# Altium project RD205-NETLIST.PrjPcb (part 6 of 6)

## Sheet 13.SchDoc
size 398 x 287 mm
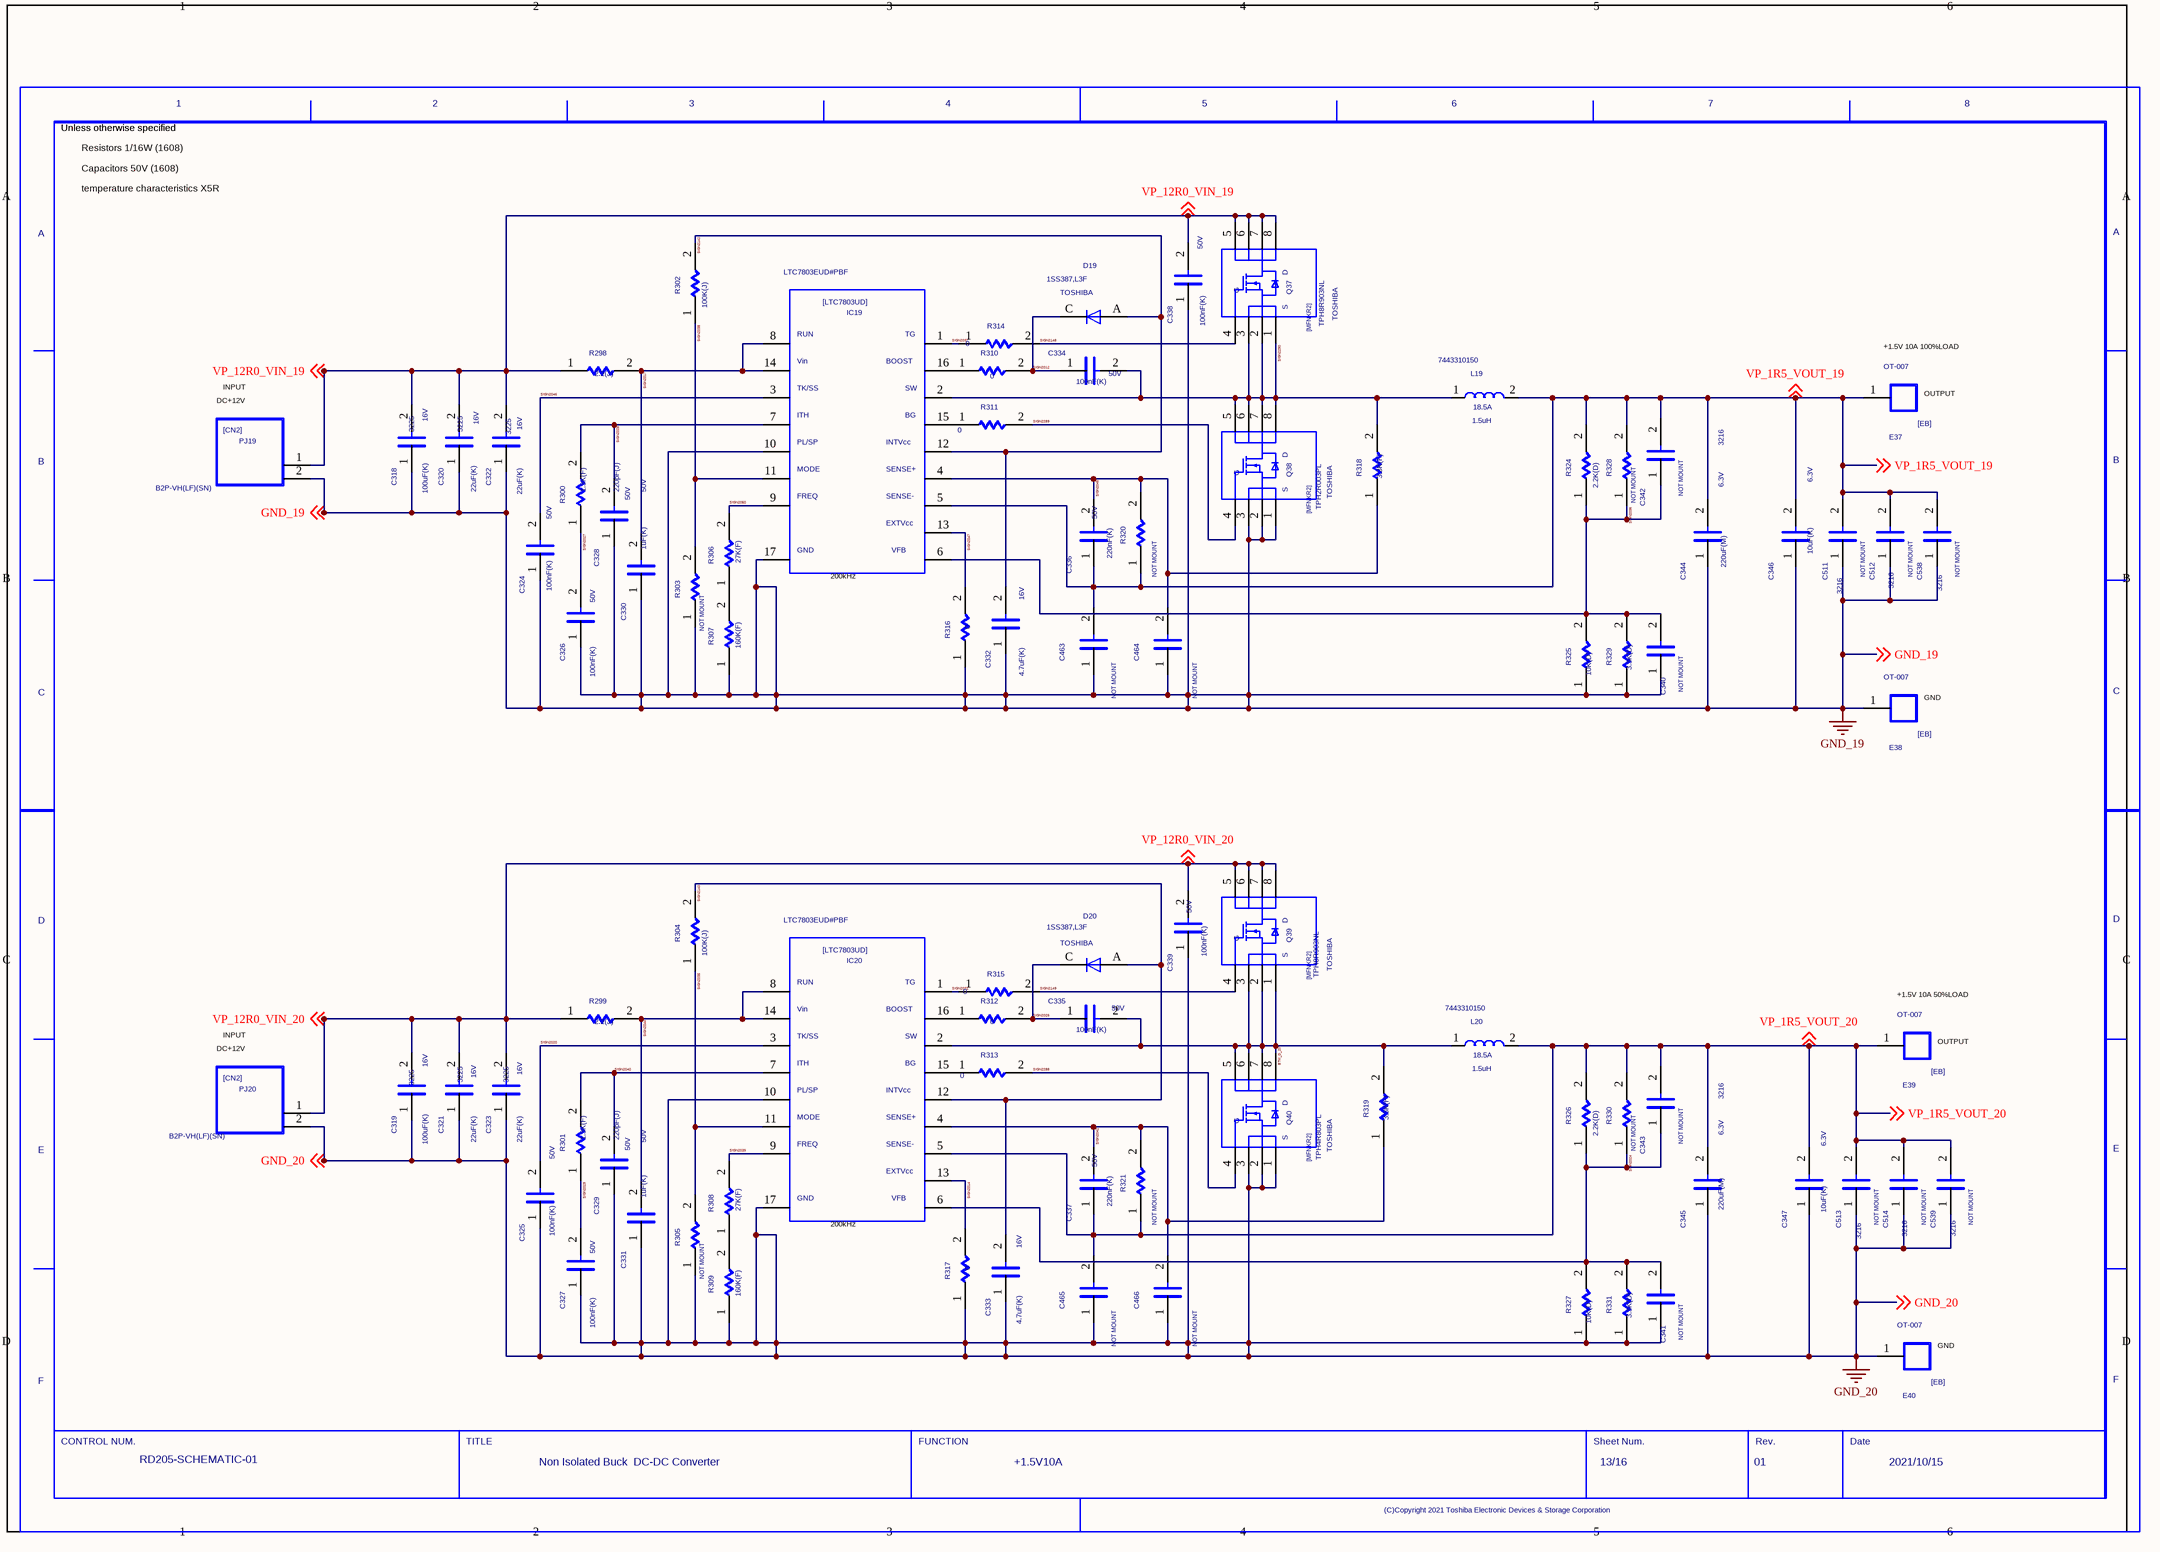
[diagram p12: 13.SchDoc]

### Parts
(Parts that share a designator on the sheet are numbered #1, #2 ... from top to bottom, then left to right.)
C318  SIZECODESMD: 3225  VAL2: 16V  VAL1: 100uF(K)  (hidden comment: C)
C319  SIZECODESMD: 3225  VAL2: 16V  VAL1: 100uF(K)  (hidden comment: C)
C320  SIZECODESMD: 3225  VAL2: 16V  VAL1: 22uF(K)  (hidden comment: C)
C321  SIZECODESMD: 3225  VAL2: 16V  VAL1: 22uF(K)  (hidden comment: C)
C322  SIZECODESMD: 3225  VAL2: 16V  VAL1: 22uF(K)  (hidden comment: C)
C323  SIZECODESMD: 3225  VAL2: 16V  VAL1: 22uF(K)  (hidden comment: C)
C324  VAL2: 50V  VAL1: 100nF(K)  (hidden comment: C)
C325  VAL2: 50V  VAL1: 100nF(K)  (hidden comment: C)
C326  VAL2: 50V  VAL1: 100nF(K)  (hidden comment: C)
C327  VAL2: 50V  VAL1: 100nF(K)  (hidden comment: C)
C328  VAL2: 50V  VAL1: 220pF(J)  (hidden comment: C)
C329  VAL2: 50V  VAL1: 220pF(J)  (hidden comment: C)
C330  VAL2: 50V  VAL1: 1uF(K)  (hidden comment: C)
C331  VAL2: 50V  VAL1: 1uF(K)  (hidden comment: C)
C332  VAL2: 16V  VAL1: 4.7uF(K)  (hidden comment: C)
C333  VAL2: 16V  VAL1: 4.7uF(K)  (hidden comment: C)
C334  VAL2: 50V  VAL1: 100nF(K)  (hidden comment: C)
C335  VAL2: 50V  VAL1: 100nF(K)  (hidden comment: C)
C336  VAL2: 50V  VAL1: 220nF(K)  (hidden comment: C)
C337  VAL2: 50V  VAL1: 220nF(K)  (hidden comment: C)
C338  VAL2: 50V  VAL1: 100nF(K)  (hidden comment: C)
C339  VAL2: 50V  VAL1: 100nF(K)  (hidden comment: C)
C340  NOTMOUNT: NOT MOUNT  (hidden comment: C)
C341  NOTMOUNT: NOT MOUNT  (hidden comment: C)
C342  NOTMOUNT: NOT MOUNT  (hidden comment: C)
C343  NOTMOUNT: NOT MOUNT  (hidden comment: C)
C344  SIZECODESMD: 3216  VAL2: 6.3V  VAL1: 220uF(M)  (hidden comment: C)
C345  SIZECODESMD: 3216  VAL2: 6.3V  VAL1: 220uF(M)  (hidden comment: C)
C346  VAL2: 6.3V  VAL1: 10uF(K)  (hidden comment: C)
C347  VAL2: 6.3V  VAL1: 10uF(K)  (hidden comment: C)
C463  NOTMOUNT: NOT MOUNT  (hidden comment: C)
C464  NOTMOUNT: NOT MOUNT  (hidden comment: C)
C465  NOTMOUNT: NOT MOUNT  (hidden comment: C)
C466  NOTMOUNT: NOT MOUNT  (hidden comment: C)
C511  NOTMOUNT: NOT MOUNT  SIZECODESMD: 3216  (hidden comment: C)
C512  NOTMOUNT: NOT MOUNT  SIZECODESMD: 3216  (hidden comment: C)
C513  NOTMOUNT: NOT MOUNT  SIZECODESMD: 3216  (hidden comment: C)
C514  NOTMOUNT: NOT MOUNT  SIZECODESMD: 3216  (hidden comment: C)
C538  NOTMOUNT: NOT MOUNT  SIZECODESMD: 3216  (hidden comment: C)
C539  NOTMOUNT: NOT MOUNT  SIZECODESMD: 3216  (hidden comment: C)
D19  USERCOMPTEXT3: TOSHIBA  VAL3: 1SS387,L3F  (hidden comment: D)
D20  USERCOMPTEXT3: TOSHIBA  VAL3: 1SS387,L3F  (hidden comment: D)
E37  VAL3: OT-007  (hidden comment: EB)
E38  VAL3: OT-007  (hidden comment: EB)
E39  VAL3: OT-007  (hidden comment: EB)
E40  VAL3: OT-007  (hidden comment: EB)
IC19  VAL3: LTC7803EUD#PBF  (hidden comment: LTC7803UD)
IC20  VAL3: LTC7803EUD#PBF  (hidden comment: LTC7803UD)
L19  VAL3: 7443310150  VAL2: 18.5A  VAL1: 1.5uH  (hidden comment: L)
L20  VAL3: 7443310150  VAL2: 18.5A  VAL1: 1.5uH  (hidden comment: L)
PJ19  VAL3: B2P-VH(LF)(SN)  (hidden comment: CN2)
PJ20  VAL3: B2P-VH(LF)(SN)  (hidden comment: CN2)
Q37  USERCOMPTEXT3: TOSHIBA  VAL3: TPH8R903NL  (hidden comment: MFNKR2)
Q38  USERCOMPTEXT3: TOSHIBA  VAL3: TPH2R003PL  (hidden comment: MFNKR2)
Q39  USERCOMPTEXT3: TOSHIBA  VAL3: TPH8R903NL  (hidden comment: MFNKR2)
Q40  USERCOMPTEXT3: TOSHIBA  VAL3: TPH4R803PL  (hidden comment: MFNKR2)
R298  VAL1: 2.2(J)  (hidden comment: R)
R299  VAL1: 2.2(J)  (hidden comment: R)
R300  VAL1: 1.3K(F)  (hidden comment: R)
R301  VAL1: 1.3K(F)  (hidden comment: R)
R302  VAL1: 100K(J)  (hidden comment: R)
R303  NOTMOUNT: NOT MOUNT  (hidden comment: R)
R304  VAL1: 100K(J)  (hidden comment: R)
R305  NOTMOUNT: NOT MOUNT  (hidden comment: R)
R306  VAL1: 27K(F)  (hidden comment: R)
R307  VAL1: 160K(F)  (hidden comment: R)
R308  VAL1: 27K(F)  (hidden comment: R)
R309  VAL1: 160K(F)  (hidden comment: R)
R310  VAL1: 0  (hidden comment: R)
R311  VAL1: 0  (hidden comment: R)
R312  VAL1: 0  (hidden comment: R)
R313  VAL1: 0  (hidden comment: R)
R314  VAL1: 0  (hidden comment: R)
R315  VAL1: 0  (hidden comment: R)
R316  VAL1: 0  (hidden comment: R)
R317  VAL1: 0  (hidden comment: R)
R318  VAL1: 3.3K(F)  (hidden comment: R)
R319  VAL1: 3.3K(F)  (hidden comment: R)
R320  NOTMOUNT: NOT MOUNT  (hidden comment: R)
R321  NOTMOUNT: NOT MOUNT  (hidden comment: R)
R324  VAL1: 2.2K(D)  (hidden comment: R)
R325  VAL1: 10K(D)  (hidden comment: R)
R326  VAL1: 2.2K(D)  (hidden comment: R)
R327  VAL1: 10K(D)  (hidden comment: R)
R328  NOTMOUNT: NOT MOUNT  (hidden comment: R)
R329  VAL1: 3.3K(D)  (hidden comment: R)
R330  NOTMOUNT: NOT MOUNT  (hidden comment: R)
R331  VAL1: 3.3K(D)  (hidden comment: R)
U?#13  DATE: 2021/10/15  SHEETNUMBER: 13/16  TITLE: Non Isolated Buck / DC-DC Converter  REVISION: 01  DRAWINGNUMBER: RD205-SCHEMATIC-01  FUNCTION: +1.5V10A  (hidden comment: WAKU_DEF100)

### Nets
GND_19: C318.1 C320.1 C322.1 C324.1 C326.1 C328.1 C330.1 C332.1 C338.1 C340.1 C344.1 C346.1 C463.1 C464.1 C511.1 C512.1 C538.1 E38.1 IC19.10 IC19.17 PJ19.2 Q38.1 Q38.2 Q38.3 R303.1 R307.1 R316.1 R325.1 R329.1 ; off-sheet GND_19
GND_20: C319.1 C321.1 C323.1 C325.1 C327.1 C329.1 C331.1 C333.1 C339.1 C341.1 C345.1 C347.1 C465.1 C466.1 C513.1 C514.1 C539.1 E40.1 IC20.10 IC20.17 PJ20.2 Q40.1 Q40.2 Q40.3 R305.1 R309.1 R317.1 R327.1 R331.1 ; off-sheet GND_20
BTM_D_20: C335.2 IC20.2 L20.1 Q39.1 Q39.2 Q39.3 Q40.5 Q40.6 Q40.7 Q40.8 R319.2
SIGN2012: C334.1 D19.C R310.2
SIGN2014: IC20.13 R317.2
SIGN2017: C330.2 IC19.8 IC19.14 R298.2
SIGN2020: C325.2 IC20.3
SIGN2024: C341.2 C343.1 IC20.6 R326.1 R327.2 R330.1 R331.2
SIGN2026: C335.1 D20.C R312.2
SIGN2027: C326.2 R300.1
SIGN2028: C328.2 IC19.7 R300.2
SIGN2029: C327.2 R301.1
SIGN2031: IC20.1 R315.1
SIGN2035: IC20.11 R304.1 R305.2
SIGN2036: C340.2 C342.1 IC19.6 R324.1 R325.2 R328.1 R329.2
SIGN2037: IC19.1 R314.1
SIGN2038: IC19.11 R302.1 R303.2
SIGN2039: IC20.9 R308.2
SIGN2040: C329.2 IC20.7 R301.2
SIGN2042: C337.2 C466.2 IC20.4 R319.1 R321.2
SIGN2044: C331.2 IC20.8 IC20.14 R299.2
SIGN2045: C336.2 C464.2 IC19.4 R318.1 R320.2
SIGN2046: C324.2 IC19.3
SIGN2047: IC19.13 R316.2
SIGN2050: IC19.9 R306.2
SIGN2142: C332.2 D19.A IC19.12 R302.2
SIGN2143: C333.2 D20.A IC20.12 R304.2
SIGN2148: Q37.4 R314.2
SIGN2149: Q39.4 R315.2
SIGN2288: Q40.4 R313.2
SIGN2289: Q38.4 R311.2
SIGN2290: C334.2 IC19.2 L19.1 Q37.1 Q37.2 Q37.3 Q38.5 Q38.6 Q38.7 Q38.8 R318.2
VP_1R5_VOUT_19: C336.1 C342.2 C344.2 C346.2 C463.2 C511.2 C512.2 C538.2 E37.1 IC19.5 L19.2 R320.1 R324.2 R328.2 ; off-sheet VP_1R5_VOUT_19
VP_1R5_VOUT_20: C337.1 C343.2 C345.2 C347.2 C465.2 C513.2 C514.2 C539.2 E39.1 IC20.5 L20.2 R321.1 R326.2 R330.2 ; off-sheet VP_1R5_VOUT_20
VP_12R0_VIN_19: C318.2 C320.2 C322.2 C338.2 PJ19.1 Q37.5 Q37.6 Q37.7 Q37.8 R298.1 ; off-sheet VP_12R0_VIN_19
VP_12R0_VIN_20: C319.2 C321.2 C323.2 C339.2 PJ20.1 Q39.5 Q39.6 Q39.7 Q39.8 R299.1 ; off-sheet VP_12R0_VIN_20
NetIC19_15: IC19.15 R311.1
NetIC19_16: IC19.16 R310.1
NetIC20_15: IC20.15 R313.1
NetIC20_16: IC20.16 R312.1
NetR306_1: R306.1 R307.2
NetR308_1: R308.1 R309.2

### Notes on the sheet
- Unless otherwise specified
- Resistors 1/16W (1608)
- Capacitors 50V (1608)
- temperature characteristics X5R
- DC+12V
- INPUT
- (near E37) +1.5V 10A 100%LOAD
- (near E37) OUTPUT
- (near IC19) 200kHz
- (near E38) GND
- (near E39) +1.5V 10A 50%LOAD
- (near E39) OUTPUT
- (near IC20) 200kHz
- (near E40) GND

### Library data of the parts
C318 C319 = C: SQ_PART_MODEL: CON_100n; FNPARTSNAMEG: CHIP CERAMIC CAPACITOR (3225); USEINPARTSLIST: YES; OriginalSymbolOrigin: (2540,7620); MFSOLDERINGPROP: .; TEMPCHARACTERI2: B; MFFORMINGDIVP: KC; OUMECLASSIFICATION: セラミックコンデンサ; MFMOUNTSYMBOLP: 90; CDMASTERCADCELG: DC903A; PCODE: P03276001115; FNCLASSCODEG: P03-03; MAXGCOUNT: 1; RATEDVOLTAGE: 250; COMPONENTNAME: G36030160049; OUMEMAKER: KYC 京セラ; MFPACKAGEMETHOP: S; NOMINALCAPACITA: 100n; OUMEMAKERKATAMEI: CF32W5R104K250AT; CAPACITANCETOLE: K
C320-C323 = C: SQ_PART_MODEL: CON_22u; FNPARTSNAMEG: CHIP CERAMIC CAPACITOR (3225); USEINPARTSLIST: YES; OriginalSymbolOrigin: (2540,7620); MFSOLDERINGPROP: .; TEMPCHARACTERI2: B; MFFORMINGDIVP: KC; OUMECLASSIFICATION: セラミックコンデンサ; MFMOUNTSYMBOLP: 80; CDMASTERCADCELG: DC903A; PCODE: P03043035626; FNCLASSCODEG: P03-03; MAXGCOUNT: 1; RATEDVOLTAGE: 6.3; COMPONENTNAME: G36030119054; OUMEMAKER: TYD 太陽誘電; MFPACKAGEMETHOP: S; NOMINALCAPACITA: 22u; OUMEMAKERKATAMEI: JMK325BJ226KM-T; CAPACITANCETOLE: K
C324-C327 C334 C335 C338 C339 = C: SQ_PART_MODEL: CON_100n; FNPARTSNAMEG: CHIP CERAMIC CAPACITOR (1608); USEINPARTSLIST: YES; OriginalSymbolOrigin: (2540,7620); MFSOLDERINGPROP: .; TEMPCHARACTERI2: B; MFFORMINGDIVP: KC; OUMECLASSIFICATION: セラミックコンデンサ; SIZECODESMD: 1608; MFMOUNTSYMBOLP: 80; CDMASTERCADCELG: C8100E; PCODE: P03B000000E4; FNCLASSCODEG: P03-03; MAXGCOUNT: 1; RATEDVOLTAGE: 16; COMPONENTNAME: GDM030000598; OUMEMAKER: MRT 村田製作所; MFPACKAGEMETHOP: S; NOMINALCAPACITA: 100n; OUMEMAKERKATAMEI: GRM188B11C104KA01C; CAPACITANCETOLE: K
C328 C329 = C: SQ_PART_MODEL: CON_220p; FNPARTSNAMEG: CHIP CERAMIC CAPACITOR (1608); USEINPARTSLIST: YES; OriginalSymbolOrigin: (2540,7620); CDMASTERCADCELG: C8100E; MFSOLDERINGPROP: .; TEMPCHARACTERI2: CH; MFFORMINGDIVP: KC; OUMECLASSIFICATION: セラミックコンデンサ; SIZECODESMD: 1608; MFMOUNTSYMBOLP: 80; PCODE: P03039269127; FNCLASSCODEG: P03-03; MAXGCOUNT: 1; RATEDVOLTAGE: 50; COMPONENTNAME: GDM030000578; OUMEMAKER: KYC 京セラ; MFPACKAGEMETHOP: S; NOMINALCAPACITA: 220p; OUMEMAKERKATAMEI: CM105CH221J50AT; CAPACITANCETOLE: J
C330 C331 = C: SQ_PART_MODEL: CON_1u; FNPARTSNAMEG: CHIP CERAMIC CAPACITOR (1608); USEINPARTSLIST: YES; OriginalSymbolOrigin: (2540,7620); MFSOLDERINGPROP: .; TEMPCHARACTERI2: B; MFFORMINGDIVP: KC; OUMECLASSIFICATION: セラミックコンデンサ; SIZECODESMD: 1608; MFMOUNTSYMBOLP: 80; CDMASTERCADCELG: C8100E; PCODE: P03039ACE122; FNCLASSCODEG: P03-03; MAXGCOUNT: 1; RATEDVOLTAGE: 6.3; COMPONENTNAME: G36030104159; OUMEMAKER: KYC 京セラ; MFPACKAGEMETHOP: S; NOMINALCAPACITA: 1u; OUMEMAKERKATAMEI: CM105B105K06ATN; CAPACITANCETOLE: K
C332 C333 = C: SQ_PART_MODEL: CON_4.7u; FNPARTSNAMEG: CHIP CERAMIC CAPACITOR (1608); USEINPARTSLIST: YES; OriginalSymbolOrigin: (2540,7620); MFSOLDERINGPROP: .; TEMPCHARACTERI2: B; MFFORMINGDIVP: KC; OUMECLASSIFICATION: セラミックコンデンサ; SIZECODESMD: 1608; MFMOUNTSYMBOLP: 80; CDMASTERCADCELG: C8100E; PCODE: P03B000000MS; FNCLASSCODEG: P03-03; MAXGCOUNT: 1; RATEDVOLTAGE: 4; COMPONENTNAME: GDM030000053; OUMEMAKER: KYC 京セラ; MFPACKAGEMETHOP: S; NOMINALCAPACITA: 4.7u; OUMEMAKERKATAMEI: CM105B475M04AT; CAPACITANCETOLE: M
C336 C337 = C: SQ_PART_MODEL: CON_220n; FNPARTSNAMEG: CHIP CERAMIC CAPACITOR (1608); PARTCOMMENT: 代表セル<KC0008> がフットプリントに登録されていません。; USEINPARTSLIST: YES; OriginalSymbolOrigin: (2540,7620); MFSOLDERINGPROP: .; TEMPCHARACTERI2: B; MFFORMINGDIVP: KC; OUMECLASSIFICATION: セラミックコンデンサ; SIZECODESMD: 1608; MFMOUNTSYMBOLP: 80; CDMASTERCADCELG: KC0008; PCODE: P03B000001L3; FNCLASSCODEG: P03-03; MAXGCOUNT: 1; RATEDVOLTAGE: 16; COMPONENTNAME: GDM030001129; OUMEMAKER: MRT 村田製作所; MFPACKAGEMETHOP: S; NOMINALCAPACITA: 220n; OUMEMAKERKATAMEI: GRM188B11C224KA01D; CAPACITANCETOLE: K
C340-C343 = C: SQ_PART_MODEL: CON_100p; FNPARTSNAMEG: CHIP CERAMIC CAPACITOR (1608); USEINPARTSLIST: YES; OriginalSymbolOrigin: (2540,7620); TOLERANCE: J; ASIMVALUE: 100P; MFSOLDERINGPROP: .; TEMPCHARACTERI2: CH; MFFORMINGDIVP: KC; OUMECLASSIFICATION: セラミックコンデンサ; SIZECODESMD: 1608; MFMOUNTSYMBOLP: 80; CDMASTERCADCELG: C8100E; PCODE: P03039177125; FNCLASSCODEG: P03-03; MAXGCOUNT: 1; RATEDVOLTAGE: 50; COMPONENTNAME: G36030011365; OUMEMAKER: KYC 京セラ; MFPACKAGEMETHOP: S; OUMEMAKERKATAMEI: CM105CH101J50AT; VAL2: 50V; VAL1: 100pF(J)
C344 C345 = C: SQ_PART_MODEL: CON_22u; FNPARTSNAMEG: CHIP CERAMIC CAPACITOR (3216); USEINPARTSLIST: YES; OriginalSymbolOrigin: (2540,7620); MFSOLDERINGPROP: .; TEMPCHARACTERI2: B; MFFORMINGDIVP: KC; OUMECLASSIFICATION: セラミックコンデンサ; MFMOUNTSYMBOLP: 80; CDMASTERCADCELG: DC901A; PCODE: P03B0000004V; FNCLASSCODEG: P03-03; MAXGCOUNT: 1; RATEDVOLTAGE: 6.3; COMPONENTNAME: GDM030000020; OUMEMAKER: KYC 京セラ; MFPACKAGEMETHOP: S; NOMINALCAPACITA: 22u; OUMEMAKERKATAMEI: CM316B226M06AT; CAPACITANCETOLE: M
C346 C347 = C: SQ_PART_MODEL: CON_1u; FNPARTSNAMEG: CHIP CERAMIC CAPACITOR (1608); PARTCOMMENT: 代表セル<KC0008> がフットプリントに登録されていません。; USEINPARTSLIST: YES; OriginalSymbolOrigin: (2540,7620); MFSOLDERINGPROP: .; TEMPCHARACTERI2: B; MFFORMINGDIVP: KC; OUMECLASSIFICATION: セラミックコンデンサ; SIZECODESMD: 1608; MFMOUNTSYMBOLP: 80; CDMASTERCADCELG: KC0008; PCODE: P03B000000ZQ; FNCLASSCODEG: P03-03; MAXGCOUNT: 1; RATEDVOLTAGE: 6.3; COMPONENTNAME: GDM030000202; OUMEMAKER: MRT 村田製作所; MFPACKAGEMETHOP: S; NOMINALCAPACITA: 1u; OUMEMAKERKATAMEI: GRM185B10J105KE21D; CAPACITANCETOLE: K
C463-C466 = C: SQ_PART_MODEL: CON_220n; FNPARTSNAMEG: CHIP CERAMIC CAPACITOR (1608); PARTCOMMENT: 代表セル<KC0008> がフットプリントに登録されていません。; USEINPARTSLIST: YES; OriginalSymbolOrigin: (2540,7620); MFSOLDERINGPROP: .; TEMPCHARACTERI2: B; MFFORMINGDIVP: KC; OUMECLASSIFICATION: セラミックコンデンサ; SIZECODESMD: 1608; MFMOUNTSYMBOLP: 80; CDMASTERCADCELG: KC0008; PCODE: P03B000001L3; FNCLASSCODEG: P03-03; MAXGCOUNT: 1; RATEDVOLTAGE: 16; COMPONENTNAME: GDM030001129; OUMEMAKER: MRT 村田製作所; MFPACKAGEMETHOP: S; NOMINALCAPACITA: 220n; OUMEMAKERKATAMEI: GRM188B11C224KA01D; VAL2: 16V; VAL1: 220nF(K); CAPACITANCETOLE: K
C511-C514 C538 C539 = C: SQ_PART_MODEL: CON_22u; FNPARTSNAMEG: CHIP CERAMIC CAPACITOR (3216); USEINPARTSLIST: YES; OriginalSymbolOrigin: (2540,7620); MFSOLDERINGPROP: .; TEMPCHARACTERI2: B; MFFORMINGDIVP: KC; OUMECLASSIFICATION: セラミックコンデンサ; MFMOUNTSYMBOLP: 80; CDMASTERCADCELG: DC901A; PCODE: P03B0000004V; FNCLASSCODEG: P03-03; MAXGCOUNT: 1; RATEDVOLTAGE: 6.3; COMPONENTNAME: GDM030000020; OUMEMAKER: KYC 京セラ; MFPACKAGEMETHOP: S; NOMINALCAPACITA: 22u; OUMEMAKERKATAMEI: CM316B226M06AT; VAL2: 6.3V; VAL1: 22uF(M); CAPACITANCETOLE: M
D19 D20 = D: FNPARTSNAMEG: DIODE; USEINPARTSLIST: YES; PARTNAME: GDM420000143; SAVEAREA0: -565,-171,12979,8058; SAVECOUNT: 1; TIME: 14:49:55; UPDATEUSER: 19870035; UPDATETIME: 14:20:16; OriginalSymbolOrigin: (5080,5080); FORWARDVOLTAGEM: 0; MAXREVERSEVOLTA: 80; COMPONENTNAME: GDM420000143_package; MFSOLDERINGPROP: .; OUMEMAKER: TSB 東芝（ＹＰＳＳ）; QUADMODEL: dummymodel; MFPACKAGEMETHOP: S; MFFORMINGDIVP: MM; MOUNTINGFORMSMD: SMD; OUMECLASSIFICATION: 小信号ダイオード; OUMEMAKERKATAMEI: 1SS387(TPH3,F); CDMASTERCADCELG: D8101D; PCODE: P42B0000008E; FNCLASSCODEG: P42-01
E37-E40 = EB: FNPARTSNAMEG: TERMINAL; USEINPARTSLIST: YES; PARTNAME: 5P9L1232P001; OUMEPARTTYPE: TB; OriginalSymbolOrigin: (2540,12700); COMPONENTNAME: 5P9L1232P001_package; MAXGCOUNT: 1; MFSOLDERINGPROP: .; OUMEMAKER: オサダ; QUADMODEL: dummymodel; MFPACKAGEMETHOP: I; MFFORMINGDIVP: OD; OUMECLASSIFICATION: 端子台、端子板; CDMASTERCADCELG: DE0009; KIND: PBS; PCODE: P29045001117; TERMINALSTYLE: SC; FNCLASSCODEG: P29-01
IC19 IC20 = LTC7803UD: USEINPARTSLIST: YES; SAVECOUNT: 29; SAVEAREA0: -53177,0,89020,58420; TIME: 16:14:14; UPDATEUSER: q91866sr; UPDATETIME: 13:15:36; OriginalSymbolOrigin: (5080,55880); MAXGCOUNT: 1; COMPONENTNAME: LTC7803UD_LTC7803UD; OUMEMAKER: ANALOG DEVICES
L19 L20 = L: USEINPARTSLIST: YES; PARTNAME: 7443310047; OriginalSymbolOrigin: (2540,5080); COMPONENTNAME: L_L; MAXGCOUNT: 1; OUMEMAKER: WURTH
PJ19 PJ20 = CN2: FNPARTSNAMEG: 3.96PITCH NYLON CONNECTOR; USEINPARTSLIST: YES; PARTNAME: G36220114012; OUMEPARTTYPE: CN; OriginalSymbolOrigin: (2540,15240); MAXGCOUNT: 1; RATEDCURRENT: 7; COMPONENTNAME: G36220114012_package; MFSOLDERINGPROP: .; OUMEMAKER: JST 日本圧着端子製造; NUMBEROFCONTACT: 2; QUADMODEL: dummymodel; MFPACKAGEMETHOP: I; MFFORMINGDIVP: CU; CONTACTPITCH: 3.96m; OUMEMAKERKATAMEI: B2P-VH; CDMASTERCADCELG: DPJ514; PCODE: P22346001114; TERMINALSTYLE: PW; FNCLASSCODEG: P22-10
Q37-Q40 = MFNKR2: USEINPARTSLIST: YES; PARTNAME: TPH6R003NL; SAVEAREA0: -9199,-39,32138,22820; TIME: 18:57:44; UPDATEUSER: q91866sr; UPDATETIME: 12:36:02; SAVECOUNT: 10; OriginalSymbolOrigin: (5080,20320); MAXGCOUNT: 1; COMPONENTNAME: MFNKR2_MFNKR2
R298 R299 = R: SQ_PART_MODEL: RES_2.2; FNPARTSNAMEG: CHIP RESISTOR (1608); USEINPARTSLIST: YES; OriginalSymbolOrigin: (5080,5080); TOLERANCE: J; ASIMVALUE: 2.2; MAXGCOUNT: 1; COMPONENTNAME: G36010011507; MFSOLDERINGPROP: .; OUMEMAKER: NAE 松下電子部品; MFPACKAGEMETHOP: S; MFFORMINGDIVP: KC; MOUNTINGFORMSMD: SMD; OUMECLASSIFICATION: 表面実装用固定抵抗器; MFMOUNTSYMBOLP: 80; POWERRATING: 63m; OUMEMAKERKATAMEI: ERJ3GEYJ2R2V; NUMBEROFELEMENT: 0; VAL2: 62.5mW; CDMASTERCADCELG: DR802R; PCODE: P01042157622; FNCLASSCODEG: P01-08
R300 R301 = R: SQ_PART_MODEL: RES_1.3K; FNPARTSNAMEG: CHIP RESISTOR (1608); USEINPARTSLIST: YES; OriginalSymbolOrigin: (5080,5080); TOLERANCE: F; ASIMVALUE: 1.3K; MAXGCOUNT: 1; COMPONENTNAME: G36010104049; MFSOLDERINGPROP: .; OUMEMAKER: HDK 北陸電気工業; MFPACKAGEMETHOP: S; MFFORMINGDIVP: KC; MOUNTINGFORMSMD: SMD; OUMECLASSIFICATION: 表面実装用固定抵抗器; MFMOUNTSYMBOLP: 80; POWERRATING: 63m; OUMEMAKERKATAMEI: CR1/16 132FV; NUMBEROFELEMENT: 0; VAL2: 62.5mW; CDMASTERCADCELG: DR802R; PCODE: P01042017223; FNCLASSCODEG: P01-08
R302 R304 = R: SQ_PART_MODEL: RES_100K; FNPARTSNAMEG: CHIP RESISTOR (1608); USEINPARTSLIST: YES; OriginalSymbolOrigin: (5080,5080); TOLERANCE: J; ASIMVALUE: 100K; MFSOLDERINGPROP: .; MFPACKAGEMETHOP: S; MFFORMINGDIVP: KC; MOUNTINGFORMSMD: SMD; MFMOUNTSYMBOLP: 80; NUMBEROFELEMENT: 0; PCODE: P01042047220; MAXGCOUNT: 1; COMPONENTNAME: G36010011057; OUMEMAKER: HDK 北陸電気工業; OUMECLASSIFICATION: 表面実装用固定抵抗器; POWERRATING: 63m; OUMEMAKERKATAMEI: CR1/16 104JV; VAL2: 62.5mW; CDMASTERCADCELG: DR802R; FNCLASSCODEG: P01-08
R303 R305 = R: SQ_PART_MODEL: RES_10; FNPARTSNAMEG: CHIP RESISTOR (1608); USEINPARTSLIST: YES; OriginalSymbolOrigin: (5080,5080); TOLERANCE: F; ASIMVALUE: 10; MFSOLDERINGPROP: .; MFPACKAGEMETHOP: S; MFFORMINGDIVP: KC; MOUNTINGFORMSMD: SMD; MFMOUNTSYMBOLP: 80; NUMBEROFELEMENT: 0; PCODE: P01042036620; MAXGCOUNT: 1; COMPONENTNAME: G36010104063; OUMEMAKER: NAE 松下電子部品; OUMECLASSIFICATION: 表面実装用固定抵抗器; POWERRATING: 63m; OUMEMAKERKATAMEI: ERJ3GEYF100V; VAL2: 62.5mW; VAL1: 10(F); CDMASTERCADCELG: DR802R; FNCLASSCODEG: P01-08
R306 R308 = R: SQ_PART_MODEL: RES_27K; FNPARTSNAMEG: CHIP RESISTOR (1608); USEINPARTSLIST: YES; OriginalSymbolOrigin: (5080,5080); MAXGCOUNT: 1; TOLERANCE: F; COMPONENTNAME: G36010027195; MFSOLDERINGPROP: .; OUMEMAKER: NAE 松下電子部品; MFPACKAGEMETHOP: S; MFFORMINGDIVP: KC; MOUNTINGFORMSMD: SMD; OUMECLASSIFICATION: 表面実装用固定抵抗器; ASIMVALUE: 27K; MFMOUNTSYMBOLP: 80; POWERRATING: 63m; OUMEMAKERKATAMEI: ERJ3GEYF273V; NUMBEROFELEMENT: 0; VAL2: 62.5mW; CDMASTERCADCELG: DR802R; PCODE: P01042508622; FNCLASSCODEG: P01-08
R307 R309 = R: SQ_PART_MODEL: RES_160K; FNPARTSNAMEG: CHIP RESISTOR (1608); USEINPARTSLIST: YES; OriginalSymbolOrigin: (5080,5080); MAXGCOUNT: 1; COMPONENTNAME: G51011061108; MFSOLDERINGPROP: .; OUMEMAKER: HDK 北陸電気工業; MFPACKAGEMETHOP: S; MFFORMINGDIVP: KC; MOUNTINGFORMSMD: SMD; OUMECLASSIFICATION: 表面実装用固定抵抗器; RESISTANCETOLER: F; MFMOUNTSYMBOLP: 80; POWERRATING: 63m; OUMEMAKERKATAMEI: CR1/16 164FV; NOMINALRESISTAN: 160K; NUMBEROFELEMENT: 0; VAL2: 62.5mW; CDMASTERCADCELG: DR802R; PCODE: P01042125225; FNCLASSCODEG: P01-08
R310 R312 R316 R317 = R: SQ_PART_MODEL: RES_10; FNPARTSNAMEG: CHIP RESISTOR (1608); USEINPARTSLIST: YES; OriginalSymbolOrigin: (5080,5080); TOLERANCE: F; ASIMVALUE: 10; MFSOLDERINGPROP: .; MFPACKAGEMETHOP: S; MFFORMINGDIVP: KC; MOUNTINGFORMSMD: SMD; MFMOUNTSYMBOLP: 80; PCODE: P01042036620; MAXGCOUNT: 1; COMPONENTNAME: G36010104063; OUMEMAKER: NAE 松下電子部品; OUMECLASSIFICATION: 表面実装用固定抵抗器; POWERRATING: 63m; OUMEMAKERKATAMEI: ERJ3GEYF100V; VAL2: 62.5mW; CDMASTERCADCELG: DR802R; FNCLASSCODEG: P01-08
R311 R313-R315 = R: SQ_PART_MODEL: RES_10; FNPARTSNAMEG: CHIP RESISTOR (2012); USEINPARTSLIST: YES; OriginalSymbolOrigin: (5080,5080); MAXGCOUNT: 1; TOLERANCE: F; COMPONENTNAME: 5P9L1083P100; MFSOLDERINGPROP: .; OUMEMAKER: 北陸電気工業; MFPACKAGEMETHOP: S; MFFORMINGDIVP: KC; MOUNTINGFORMSMD: SMD; OUMECLASSIFICATION: 表面実装用固定抵抗器; ASIMVALUE: 10; MFMOUNTSYMBOLP: 90; POWERRATING: 100m; OUMEMAKERKATAMEI: CR1/10 100FV Pb(F); VAL2: 125mW; CDMASTERCADCELG: DR910A; PCODE: P01043091222; FNCLASSCODEG: P01-08
R318 R319 = R: SQ_PART_MODEL: RES_3.3K; FNPARTSNAMEG: CHIP RESISTOR (1608); USEINPARTSLIST: YES; OriginalSymbolOrigin: (5080,5080); TOLERANCE: F; ASIMVALUE: 3.3K; MAXGCOUNT: 1; COMPONENTNAME: G36010027027; MFSOLDERINGPROP: .; OUMEMAKER: ROH ロー・; MFPACKAGEMETHOP: S; MFFORMINGDIVP: KC; MOUNTINGFORMSMD: SMD; OUMECLASSIFICATION: 表面実装用固定抵抗器; MFMOUNTSYMBOLP: 80; POWERRATING: 63m; OUMEMAKERKATAMEI: MCR03EZPFX3301; NUMBEROFELEMENT: 0; VAL2: 62.5mW; CDMASTERCADCELG: DR802R; PCODE: P01042250729; FNCLASSCODEG: P01-08
R320 R321 = R: SQ_PART_MODEL: RES_68K; FNPARTSNAMEG: CHIP RESISTOR (1608); USEINPARTSLIST: YES; OriginalSymbolOrigin: (5080,5080); TOLERANCE: F; ASIMVALUE: 68K; MAXGCOUNT: 1; COMPONENTNAME: G36010027126; MFSOLDERINGPROP: .; OUMEMAKER: HDK 北陸電気工業; MFPACKAGEMETHOP: S; MFFORMINGDIVP: KC; MOUNTINGFORMSMD: SMD; OUMECLASSIFICATION: 表面実装用固定抵抗器; MFMOUNTSYMBOLP: 80; POWERRATING: 63m; OUMEMAKERKATAMEI: CR1/16 683FV; NUMBEROFELEMENT: 0; VAL2: 62.5mW; VAL1: 68K(F); CDMASTERCADCELG: DR802R; PCODE: P01042456220; FNCLASSCODEG: P01-08
R324 R326 = R: SQ_PART_MODEL: RES_2.2K; FNPARTSNAMEG: CHIP RESISTOR (1608); USEINPARTSLIST: YES; OriginalSymbolOrigin: (5080,5080); MAXGCOUNT: 1; COMPONENTNAME: G36010129332; MFSOLDERINGPROP: .; OUMEMAKER: NAE 松下電子部品; MFPACKAGEMETHOP: S; MFFORMINGDIVP: KC; MOUNTINGFORMSMD: SMD; OUMECLASSIFICATION: 表面実装用固定抵抗器; RESISTANCETOLER: D; MFMOUNTSYMBOLP: 80; POWERRATING: 63m; OUMEMAKERKATAMEI: ERJ3RBD222V; NOMINALRESISTAN: 2.2K; NUMBEROFELEMENT: 0; VAL2: 62.5mW; CDMASTERCADCELG: DR802R; PCODE: P01119035112; FNCLASSCODEG: P01-08
R325 R327 = R: ICX_PART_MODEL: RES_10K; FNPARTSNAMEG: CHIP RESISTOR (1608); OriginalSymbolOrigin: (5080,5080); FNCLASSCODEG: P01-08; PCODE: P01117053118; CDMASTERCADCELG: DR802R; USEWITHSCHEMA: YES; VAL2: 62.5mW; NUMBEROFELEMENT: 0; NOMINALRESISTAN: 10K; OUMEMAKERKATAMEI: RK73G1JTD103D; POWERRATING: 63m; MFMOUNTSYMBOLP: 80; RESISTANCETOLER: D; FUNCTION: G36010129493; OUMECLASSIFICATION: 表面実装用固定抵抗器; MOUNTINGFORMSMD: SMD; MFFORMINGDIVP: KC; MFPACKAGEMETHOP: S; OUMEMAKER: KOA ＫＯＡ; MFSOLDERINGPROP: .; MAXGCOUNT: 1
R328 R330 = R: SQ_PART_MODEL: RES_3.3K; FNPARTSNAMEG: CHIP RESISTOR (1608); USEINPARTSLIST: YES; OriginalSymbolOrigin: (5080,5080); TOLERANCE: F; ASIMVALUE: 3.3K; MAXGCOUNT: 1; COMPONENTNAME: G36010027027; MFSOLDERINGPROP: .; OUMEMAKER: ROH ロー・; MFPACKAGEMETHOP: S; MFFORMINGDIVP: KC; MOUNTINGFORMSMD: SMD; OUMECLASSIFICATION: 表面実装用固定抵抗器; MFMOUNTSYMBOLP: 80; POWERRATING: 63m; OUMEMAKERKATAMEI: MCR03EZPFX3301; NUMBEROFELEMENT: 0; VAL2: 62.5mW; VAL1: 3.3K(F); CDMASTERCADCELG: DR802R; PCODE: P01042250729; FNCLASSCODEG: P01-08
R329 = R: ICX_PART_MODEL: RES_3.3K; FNPARTSNAMEG: CHIP RESISTOR (1608); OriginalSymbolOrigin: (5080,5080); FNCLASSCODEG: P01-08; PCODE: P01042249822; CDMASTERCADCELG: DR802R; USEWITHSCHEMA: YES; VAL2: 62.5mW; NUMBEROFELEMENT: 0; NOMINALRESISTAN: 3.3K; OUMEMAKERKATAMEI: RR0816P-332-D; POWERRATING: 63m; MFMOUNTSYMBOLP: 80; RESISTANCETOLER: D; FUNCTION: G36010014485; OUMECLASSIFICATION: 表面実装用固定抵抗器; MOUNTINGFORMSMD: SMD; MFFORMINGDIVP: KC; MFPACKAGEMETHOP: S; OUMEMAKER: SSM 進工業; MFSOLDERINGPROP: .; MAXGCOUNT: 1
R331 = R: ICX_PART_MODEL: RES_3.3K; FNPARTSNAMEG: CHIP RESISTOR (1608); OriginalSymbolOrigin: (5080,5080); FNCLASSCODEG: P01-08; PCODE: P01117041115; CDMASTERCADCELG: DR802R; USEWITHSCHEMA: YES; VAL2: 62.5mW; NUMBEROFELEMENT: 0; NOMINALRESISTAN: 3.3K; OUMEMAKERKATAMEI: RK73G1JTD332D; POWERRATING: 63m; MFMOUNTSYMBOLP: 80; RESISTANCETOLER: D; FUNCTION: G36010129370; OUMECLASSIFICATION: 表面実装用固定抵抗器; MOUNTINGFORMSMD: SMD; MFFORMINGDIVP: KC; MFPACKAGEMETHOP: S; OUMEMAKER: KOA ＫＯＡ; MFSOLDERINGPROP: .; MAXGCOUNT: 1
U?#13 = WAKU_DEF100: PLOTTIME: HH:MM; SAVEAREA0: 330961,54,387907,31546; TIME: 19:23:07; UPDATEUSER: t5459927; UPDATETIME: 15:33:42; SAVECOUNT: 6; OriginalSymbolOrigin: (10160,284480); DESIGNED: ***

## Sheet 14.SchDoc
size 398 x 287 mm
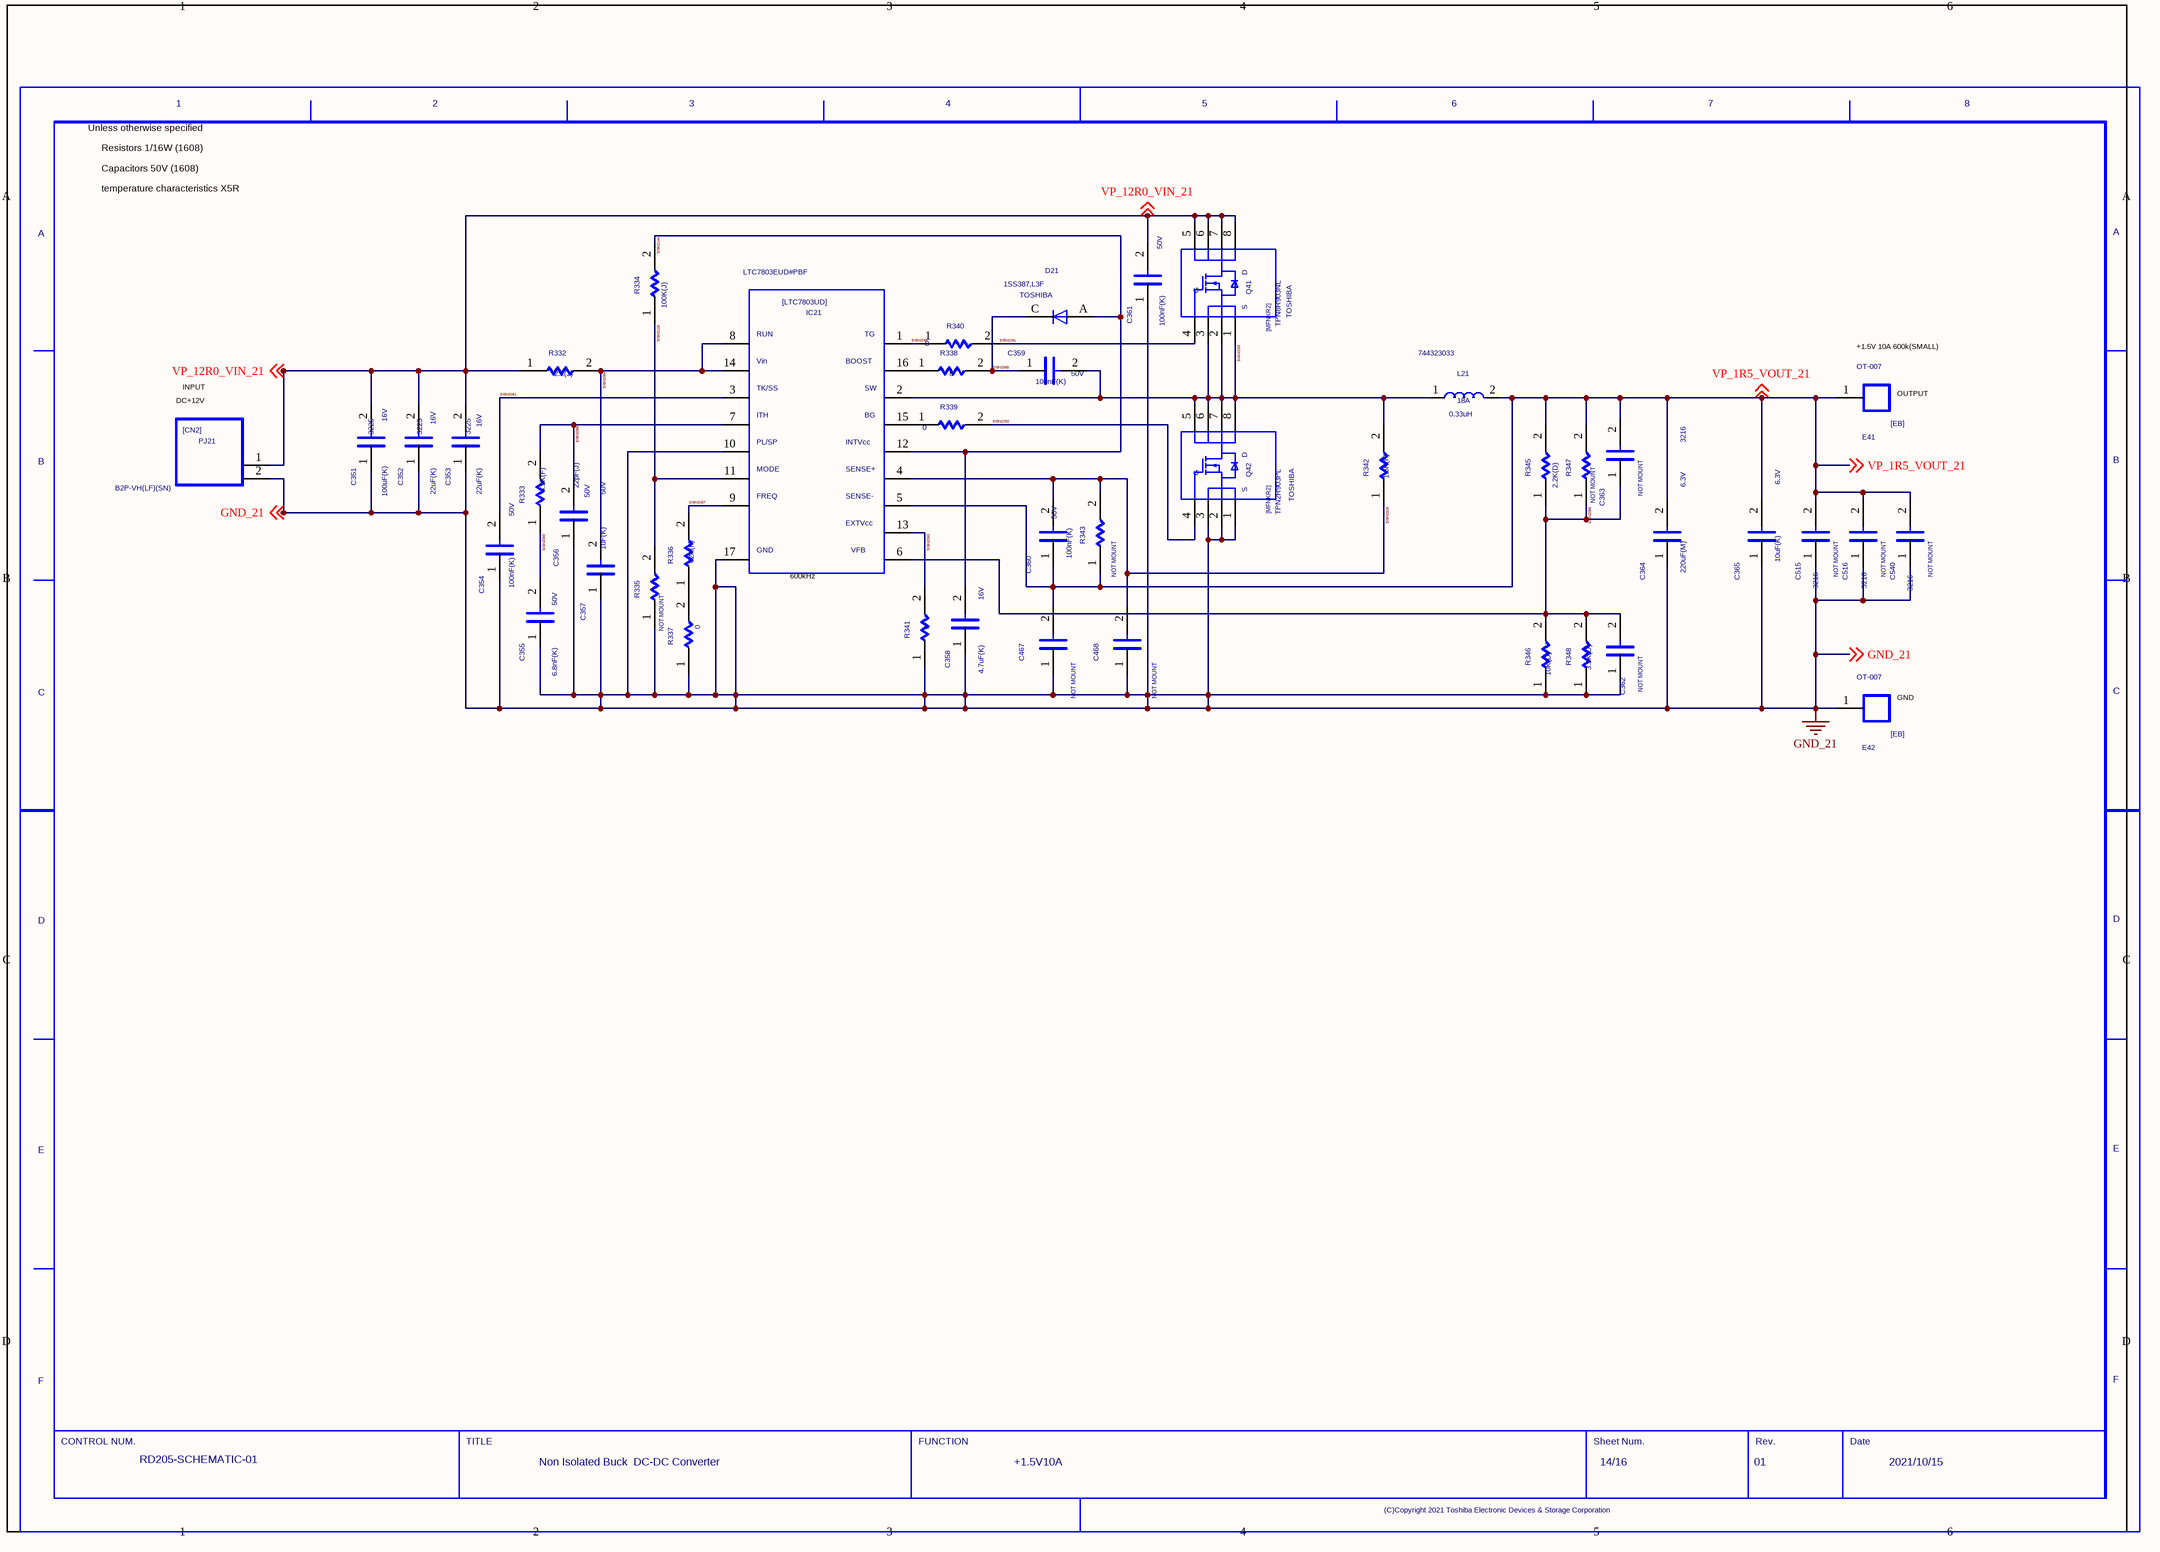
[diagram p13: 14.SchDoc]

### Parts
(Parts that share a designator on the sheet are numbered #1, #2 ... from top to bottom, then left to right.)
C351  SIZECODESMD: 3225  VAL2: 16V  VAL1: 100uF(K)  (hidden comment: C)
C352  SIZECODESMD: 3225  VAL2: 16V  VAL1: 22uF(K)  (hidden comment: C)
C353  SIZECODESMD: 3225  VAL2: 16V  VAL1: 22uF(K)  (hidden comment: C)
C354  VAL2: 50V  VAL1: 100nF(K)  (hidden comment: C)
C355  VAL2: 50V  VAL1: 6.8nF(K)  (hidden comment: C)
C356  VAL2: 50V  VAL1: 22pF(J)  (hidden comment: C)
C357  VAL2: 50V  VAL1: 1uF(K)  (hidden comment: C)
C358  VAL2: 16V  VAL1: 4.7uF(K)  (hidden comment: C)
C359  VAL2: 50V  VAL1: 100nF(K)  (hidden comment: C)
C360  VAL2: 50V  VAL1: 100nF(K)  (hidden comment: C)
C361  VAL2: 50V  VAL1: 100nF(K)  (hidden comment: C)
C362  NOTMOUNT: NOT MOUNT  (hidden comment: C)
C363  NOTMOUNT: NOT MOUNT  (hidden comment: C)
C364  SIZECODESMD: 3216  VAL2: 6.3V  VAL1: 220uF(M)  (hidden comment: C)
C365  VAL2: 6.3V  VAL1: 10uF(K)  (hidden comment: C)
C467  NOTMOUNT: NOT MOUNT  (hidden comment: C)
C468  NOTMOUNT: NOT MOUNT  (hidden comment: C)
C515  NOTMOUNT: NOT MOUNT  SIZECODESMD: 3216  (hidden comment: C)
C516  NOTMOUNT: NOT MOUNT  SIZECODESMD: 3216  (hidden comment: C)
C540  NOTMOUNT: NOT MOUNT  SIZECODESMD: 3216  (hidden comment: C)
D21  USERCOMPTEXT3: TOSHIBA  VAL3: 1SS387,L3F  (hidden comment: D)
E41  VAL3: OT-007  (hidden comment: EB)
E42  VAL3: OT-007  (hidden comment: EB)
IC21  VAL3: LTC7803EUD#PBF  (hidden comment: LTC7803UD)
L21  VAL3: 744323033  VAL2: 18A  VAL1: 0.33uH  (hidden comment: L)
PJ21  VAL3: B2P-VH(LF)(SN)  (hidden comment: CN2)
Q41  USERCOMPTEXT3: TOSHIBA  VAL3: TPN8R903NL  (hidden comment: MFNKR2)
Q42  USERCOMPTEXT3: TOSHIBA  VAL3: TPN2R903PL  (hidden comment: MFNKR2)
R332  VAL1: 2.2(J)  (hidden comment: R)
R333  VAL1: 4.3K(F)  (hidden comment: R)
R334  VAL1: 100K(J)  (hidden comment: R)
R335  NOTMOUNT: NOT MOUNT  (hidden comment: R)
R336  VAL1: 62K(F)  (hidden comment: R)
R337  VAL1: 0  (hidden comment: R)
R338  VAL1: 0  (hidden comment: R)
R339  VAL1: 0  (hidden comment: R)
R340  VAL1: 0  (hidden comment: R)
R341  VAL1: 0  (hidden comment: R)
R342  VAL1: 1.5K(F)  (hidden comment: R)
R343  NOTMOUNT: NOT MOUNT  (hidden comment: R)
R345  VAL1: 2.2K(D)  (hidden comment: R)
R346  VAL1: 10K(D)  (hidden comment: R)
R347  NOTMOUNT: NOT MOUNT  (hidden comment: R)
R348  VAL1: 3.3K(D)  (hidden comment: R)
U?#14  DATE: 2021/10/15  SHEETNUMBER: 14/16  TITLE: Non Isolated Buck / DC-DC Converter  REVISION: 01  DRAWINGNUMBER: RD205-SCHEMATIC-01  FUNCTION: +1.5V10A  (hidden comment: WAKU_DEF100)

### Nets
GND_21: C351.1 C352.1 C353.1 C354.1 C355.1 C356.1 C357.1 C358.1 C361.1 C362.1 C364.1 C365.1 C467.1 C468.1 C515.1 C516.1 C540.1 E42.1 IC21.10 IC21.17 PJ21.2 Q42.1 Q42.2 Q42.3 R335.1 R337.1 R341.1 R346.1 R348.1 ; off-sheet GND_21
SIGN2056: C362.2 C363.1 IC21.6 R345.1 R346.2 R347.1 R348.2
SIGN2058: C356.2 IC21.7 R333.2
SIGN2060: C355.2 R333.1
SIGN2061: C354.2 IC21.3
SIGN2063: IC21.13 R341.2
SIGN2064: C357.2 IC21.8 IC21.14 R332.2
SIGN2065: C359.1 D21.C R338.2
SIGN2066: IC21.1 R340.1
SIGN2067: IC21.9 R336.2
SIGN2125: IC21.11 R334.1 R335.2
SIGN2144: C358.2 D21.A IC21.12 R334.2
SIGN2291: Q41.4 R340.2
SIGN2292: Q42.4 R339.2
SIGN2293: C359.2 IC21.2 L21.1 Q41.1 Q41.2 Q41.3 Q42.5 Q42.6 Q42.7 Q42.8 R342.2
SIGN2318: C360.2 C468.2 IC21.4 R342.1 R343.2
VP_1R5_VOUT_21: C360.1 C363.2 C364.2 C365.2 C467.2 C515.2 C516.2 C540.2 E41.1 IC21.5 L21.2 R343.1 R345.2 R347.2 ; off-sheet VP_1R5_VOUT_21
VP_12R0_VIN_21: C351.2 C352.2 C353.2 C361.2 PJ21.1 Q41.5 Q41.6 Q41.7 Q41.8 R332.1 ; off-sheet VP_12R0_VIN_21
NetIC21_15: IC21.15 R339.1
NetIC21_16: IC21.16 R338.1
NetR336_1: R336.1 R337.2

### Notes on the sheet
- Unless otherwise specified
- Capacitors 50V (1608)
- Resistors 1/16W (1608)
- temperature characteristics X5R
- DC+12V
- INPUT
- (near E41) +1.5V 10A 600k(SMALL)
- (near E41) OUTPUT
- (near IC21) 600kHz
- (near E42) GND

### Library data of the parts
C351 = C: as C318 on sheet 13
C352 C353 = C: as C320-C323 on sheet 13
C354 C359 C361 = C: as C324-C327 on sheet 13
C355 = C: SQ_PART_MODEL: CON_6.8n; FNPARTSNAMEG: CHIP CERAMIC CAPACITOR (1608); USEINPARTSLIST: YES; OriginalSymbolOrigin: (2540,7620); TOLERANCE: K; ASIMVALUE: 6.8N; MFSOLDERINGPROP: .; TEMPCHARACTERI2: B; MFFORMINGDIVP: KC; OUMECLASSIFICATION: セラミックコンデンサ; SIZECODESMD: 1608; MFMOUNTSYMBOLP: 80; CDMASTERCADCELG: C8100E; PCODE: P03039109225; FNCLASSCODEG: P03-03; MAXGCOUNT: 1; RATEDVOLTAGE: 50; COMPONENTNAME: G36030011440; OUMEMAKER: MRT 村田製作所; MFPACKAGEMETHOP: S; OUMEMAKERKATAMEI: GRM39B682K50PT
C356 = C: SQ_PART_MODEL: CON_22p; FNPARTSNAMEG: CHIP CERAMIC CAPACITOR (1608); USEINPARTSLIST: YES; OriginalSymbolOrigin: (2540,7620); TOLERANCE: J; ASIMVALUE: 22P; CDMASTERCADCELG: C8100E; MFSOLDERINGPROP: .; TEMPCHARACTERI2: CH; MFFORMINGDIVP: KC; OUMECLASSIFICATION: セラミックコンデンサ; SIZECODESMD: 1608; MFMOUNTSYMBOLP: 80; PCODE: P03039A02625; FNCLASSCODEG: P03-03; MAXGCOUNT: 1; RATEDVOLTAGE: 50; COMPONENTNAME: G36030011129; OUMEMAKER: TYD 太陽誘電; MFPACKAGEMETHOP: S; OUMEMAKERKATAMEI: UMK107CH220JZ-T
C357 = C: as C330 on sheet 13
C358 = C: as C332 on sheet 13
C360 = C: SQ_PART_MODEL: CON_100n; FNPARTSNAMEG: CHIP CERAMIC CAPACITOR (1608); USEINPARTSLIST: YES; OriginalSymbolOrigin: (2540,7620); MFSOLDERINGPROP: .; TEMPCHARACTERI2: B; MFFORMINGDIVP: KC; OUMECLASSIFICATION: セラミックコンデンサ; SIZECODESMD: 1608; MFMOUNTSYMBOLP: 80; CDMASTERCADCELG: C8100E; PCODE: P03B000000E4; FNCLASSCODEG: P03-03; MAXGCOUNT: 1; RATEDVOLTAGE: 16; COMPONENTNAME: GDM030001129; OUMEMAKER: MRT 村田製作所; MFPACKAGEMETHOP: S; NOMINALCAPACITA: 100n; OUMEMAKERKATAMEI: GRM188B11C104KA01C; CAPACITANCETOLE: K
C362 C363 = C: as C340-C343 on sheet 13
C364 = C: as C344 on sheet 13
C365 = C: SQ_PART_MODEL: CON_1u; FNPARTSNAMEG: CHIP CERAMIC CAPACITOR (1608); PARTCOMMENT: 代表セル<KC0008> がフットプリントに登録されていません。; USEINPARTSLIST: YES; OriginalSymbolOrigin: (2540,7620); MFSOLDERINGPROP: .; TEMPCHARACTERI2: B; MFPACKAGEMETHOP: S; MFFORMINGDIVP: KC; MFMOUNTSYMBOLP: 80; PCODE: P03B000000ZQ; OUMECLASSIFICATION: セラミックコンデンサ; SIZECODESMD: 1608; CDMASTERCADCELG: KC0008; FNCLASSCODEG: P03-03; MAXGCOUNT: 1; RATEDVOLTAGE: 6.3; COMPONENTNAME: GDM030000202; OUMEMAKER: MRT 村田製作所; NOMINALCAPACITA: 1u; OUMEMAKERKATAMEI: GRM185B10J105KE21D; CAPACITANCETOLE: K
C467 C468 = C: as C463-C466 on sheet 13
C515 C516 C540 = C: as C511-C514 on sheet 13
D21 = D: as D19 on sheet 13
E41 E42 = EB: as E37-E40 on sheet 13
IC21 = LTC7803UD: as IC19 on sheet 13
L21 = L: USEINPARTSLIST: YES; PARTNAME: 7443310047; OriginalSymbolOrigin: (2540,5080); MAXGCOUNT: 1; COMPONENTNAME: L_L; OUMEMAKER: WURTH
PJ21 = CN2: as PJ19 on sheet 13
Q41 Q42 = MFNKR2: USEINPARTSLIST: YES; PARTNAME: TPN1R603PL; SAVEAREA0: -9199,-39,32138,22820; TIME: 18:57:44; UPDATEUSER: q91866sr; UPDATETIME: 12:36:02; SAVECOUNT: 10; OriginalSymbolOrigin: (5080,20320); MAXGCOUNT: 1; COMPONENTNAME: MFNKR2_MFNKR2
R332 = R: as R298 on sheet 13
R333 = R: SQ_PART_MODEL: RES_4.3K; FNPARTSNAMEG: CHIP RESISTOR (1608); USEINPARTSLIST: YES; OriginalSymbolOrigin: (5080,5080); PCODE: P01042335624; MAXGCOUNT: 1; COMPONENTNAME: G5101105L102; MFSOLDERINGPROP: .; OUMEMAKER: NAE 松下電子部品; MFPACKAGEMETHOP: S; MFFORMINGDIVP: KC; MOUNTINGFORMSMD: SMD; OUMECLASSIFICATION: 表面実装用固定抵抗器; RESISTANCETOLER: F; MFMOUNTSYMBOLP: 80; POWERRATING: 63m; OUMEMAKERKATAMEI: ERJ3GEYF432V; NOMINALRESISTAN: 4.3K; NUMBEROFELEMENT: 0; VAL2: 62.5mW; CDMASTERCADCELG: DR802R; FNCLASSCODEG: P01-08
R334 = R: as R302 on sheet 13
R335 = R: as R303 on sheet 13
R336 = R: SQ_PART_MODEL: RES_62K; FNPARTSNAMEG: CHIP RESISTOR (1608); USEINPARTSLIST: YES; OriginalSymbolOrigin: (5080,5080); MAXGCOUNT: 1; COMPONENTNAME: GDM010001037; MFSOLDERINGPROP: .; OUMEMAKER: NAE 松下電子部品; MFPACKAGEMETHOP: S; MFFORMINGDIVP: KC; MOUNTINGFORMSMD: SMD; OUMECLASSIFICATION: 表面実装用固定抵抗器; RESISTANCETOLER: F; MFMOUNTSYMBOLP: 80; POWERRATING: 63m; OUMEMAKERKATAMEI: ERJ3GEYF623V; NOMINALRESISTAN: 62K; NUMBEROFELEMENT: 0; VAL2: 62.5mW; CDMASTERCADCELG: DR802R; PCODE: P01042441622; FNCLASSCODEG: P01-08
R337 = R: SQ_PART_MODEL: RES_160K; FNPARTSNAMEG: CHIP RESISTOR (1608); USEINPARTSLIST: YES; OriginalSymbolOrigin: (5080,5080); MAXGCOUNT: 1; COMPONENTNAME: G51011061108; MFSOLDERINGPROP: .; OUMEMAKER: HDK 北陸電気工業; MFPACKAGEMETHOP: S; MFFORMINGDIVP: KC; MOUNTINGFORMSMD: SMD; OUMECLASSIFICATION: 表面実装用固定抵抗器; RESISTANCETOLER: F; MFMOUNTSYMBOLP: 80; POWERRATING: 63m; OUMEMAKERKATAMEI: CR1/16 164FV; NOMINALRESISTAN: 160K; VAL2: 62.5mW; CDMASTERCADCELG: DR802R; PCODE: P01042125225; FNCLASSCODEG: P01-08
R338 R341 = R: as R310 on sheet 13
R339 R340 = R: as R311 on sheet 13
R342 = R: SQ_PART_MODEL: RES_1.5K; FNPARTSNAMEG: CHIP RESISTOR (1608); USEINPARTSLIST: YES; OriginalSymbolOrigin: (5080,5080); TOLERANCE: F; ASIMVALUE: 1.5K; MAXGCOUNT: 1; COMPONENTNAME: G36010104407; MFSOLDERINGPROP: .; OUMEMAKER: HDK 北陸電気工業; MFPACKAGEMETHOP: S; MFFORMINGDIVP: KC; MOUNTINGFORMSMD: SMD; OUMECLASSIFICATION: 表面実装用固定抵抗器; MFMOUNTSYMBOLP: 80; POWERRATING: 63m; OUMEMAKERKATAMEI: CR1/16 152FV; NUMBEROFELEMENT: 0; VAL2: 62.5mW; CDMASTERCADCELG: DR802R; PCODE: P01042512223; FNCLASSCODEG: P01-08
R343 = R: SQ_PART_MODEL: RES_8.2K; FNPARTSNAMEG: CHIP RESISTOR (1608); USEINPARTSLIST: YES; OriginalSymbolOrigin: (5080,5080); TOLERANCE: F; ASIMVALUE: 8.2K; MAXGCOUNT: 1; COMPONENTNAME: G36010027188; OUMEMAKER: KAM 釜屋電機; MOUNTINGFORMSMD: SMD; OUMECLASSIFICATION: 表面実装用固定抵抗器; POWERRATING: 63m; OUMEMAKERKATAMEI: RMC1/16-822FTP; CDMASTERCADCELG: DR802R; MFSOLDERINGPROP: .; MFPACKAGEMETHOP: S; MFFORMINGDIVP: KC; MFMOUNTSYMBOLP: 80; NUMBEROFELEMENT: 0; VAL2: 62.5mW; VAL1: 8.2K(F); PCODE: P01042507328; FNCLASSCODEG: P01-08
R345 = R: as R324 on sheet 13
R346 = R: as R325 on sheet 13
R347 = R: as R328 on sheet 13
R348 = R: as R331 on sheet 13
U?#14 = WAKU_DEF100: as U?#13 on sheet 13

## Sheet 15.SchDoc
size 401 x 287 mm
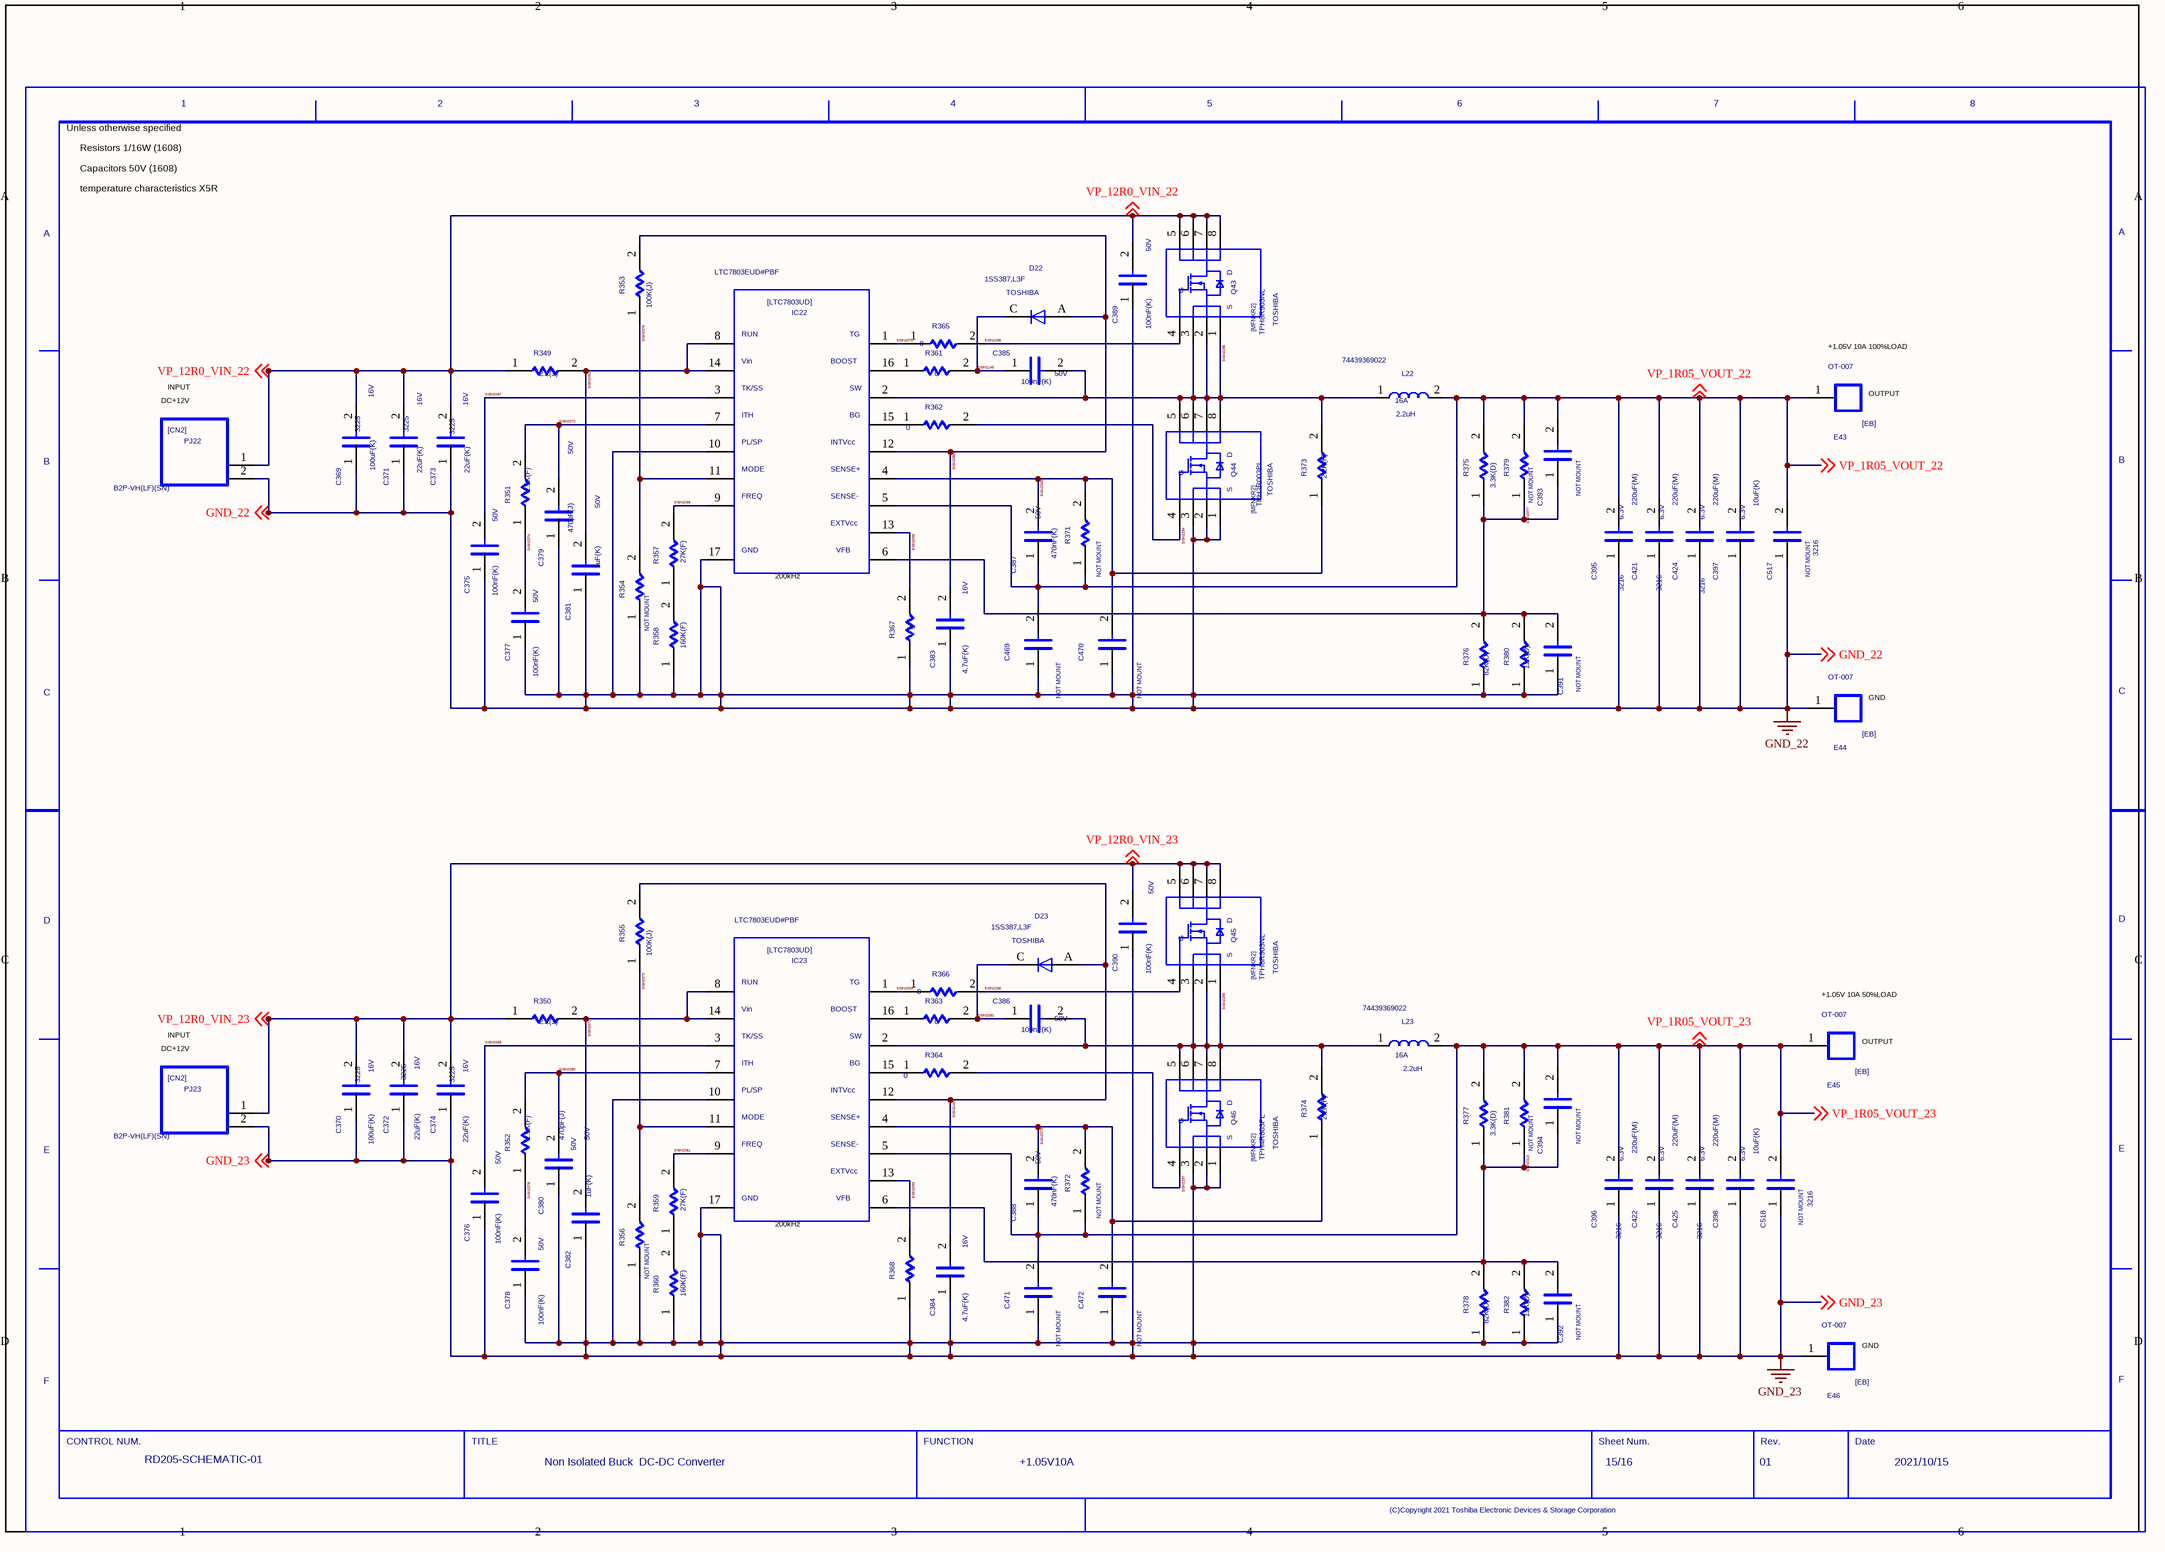
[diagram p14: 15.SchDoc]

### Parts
(Parts that share a designator on the sheet are numbered #1, #2 ... from top to bottom, then left to right.)
C369  SIZECODESMD: 3225  VAL2: 16V  VAL1: 100uF(K)  (hidden comment: C)
C370  SIZECODESMD: 3225  VAL2: 16V  VAL1: 100uF(K)  (hidden comment: C)
C371  SIZECODESMD: 3225  VAL2: 16V  VAL1: 22uF(K)  (hidden comment: C)
C372  SIZECODESMD: 3225  VAL2: 16V  VAL1: 22uF(K)  (hidden comment: C)
C373  SIZECODESMD: 3225  VAL2: 16V  VAL1: 22uF(K)  (hidden comment: C)
C374  SIZECODESMD: 3225  VAL2: 16V  VAL1: 22uF(K)  (hidden comment: C)
C375  VAL2: 50V  VAL1: 100nF(K)  (hidden comment: C)
C376  VAL2: 50V  VAL1: 100nF(K)  (hidden comment: C)
C377  VAL2: 50V  VAL1: 100nF(K)  (hidden comment: C)
C378  VAL2: 50V  VAL1: 100nF(K)  (hidden comment: C)
C379  VAL2: 50V  VAL1: 470pF(J)  (hidden comment: C)
C380  VAL2: 50V  VAL1: 470pF(J)  (hidden comment: C)
C381  VAL2: 50V  VAL1: 1uF(K)  (hidden comment: C)
C382  VAL2: 50V  VAL1: 1uF(K)  (hidden comment: C)
C383  VAL2: 16V  VAL1: 4.7uF(K)  (hidden comment: C)
C384  VAL2: 16V  VAL1: 4.7uF(K)  (hidden comment: C)
C385  VAL2: 50V  VAL1: 100nF(K)  (hidden comment: C)
C386  VAL2: 50V  VAL1: 100nF(K)  (hidden comment: C)
C387  VAL2: 50V  VAL1: 470nF(K)  (hidden comment: C)
C388  VAL2: 50V  VAL1: 470nF(K)  (hidden comment: C)
C389  VAL2: 50V  VAL1: 100nF(K)  (hidden comment: C)
C390  VAL2: 50V  VAL1: 100nF(K)  (hidden comment: C)
C391  NOTMOUNT: NOT MOUNT  (hidden comment: C)
C392  NOTMOUNT: NOT MOUNT  (hidden comment: C)
C393  NOTMOUNT: NOT MOUNT  (hidden comment: C)
C394  NOTMOUNT: NOT MOUNT  (hidden comment: C)
C395  SIZECODESMD: 3216  VAL2: 6.3V  VAL1: 220uF(M)  (hidden comment: C)
C396  SIZECODESMD: 3216  VAL2: 6.3V  VAL1: 220uF(M)  (hidden comment: C)
C397  VAL2: 6.3V  VAL1: 10uF(K)  (hidden comment: C)
C398  VAL2: 6.3V  VAL1: 10uF(K)  (hidden comment: C)
C421  SIZECODESMD: 3216  VAL2: 6.3V  VAL1: 220uF(M)  (hidden comment: C)
C422  SIZECODESMD: 3216  VAL2: 6.3V  VAL1: 220uF(M)  (hidden comment: C)
C424  SIZECODESMD: 3216  VAL2: 6.3V  VAL1: 220uF(M)  (hidden comment: C)
C425  SIZECODESMD: 3216  VAL2: 6.3V  VAL1: 220uF(M)  (hidden comment: C)
C469  NOTMOUNT: NOT MOUNT  (hidden comment: C)
C470  NOTMOUNT: NOT MOUNT  (hidden comment: C)
C471  NOTMOUNT: NOT MOUNT  (hidden comment: C)
C472  NOTMOUNT: NOT MOUNT  (hidden comment: C)
C517  NOTMOUNT: NOT MOUNT  SIZECODESMD: 3216  (hidden comment: C)
C518  NOTMOUNT: NOT MOUNT  SIZECODESMD: 3216  (hidden comment: C)
D22  USERCOMPTEXT3: TOSHIBA  VAL3: 1SS387,L3F  (hidden comment: D)
D23  USERCOMPTEXT3: TOSHIBA  VAL3: 1SS387,L3F  (hidden comment: D)
E43  VAL3: OT-007  (hidden comment: EB)
E44  VAL3: OT-007  (hidden comment: EB)
E45  VAL3: OT-007  (hidden comment: EB)
E46  VAL3: OT-007  (hidden comment: EB)
IC22  VAL3: LTC7803EUD#PBF  (hidden comment: LTC7803UD)
IC23  VAL3: LTC7803EUD#PBF  (hidden comment: LTC7803UD)
L22  VAL3: 74439369022  VAL2: 16A  VAL1: 2.2uH  (hidden comment: L)
L23  VAL3: 74439369022  VAL2: 16A  VAL1: 2.2uH  (hidden comment: L)
PJ22  VAL3: B2P-VH(LF)(SN)  (hidden comment: CN2)
PJ23  VAL3: B2P-VH(LF)(SN)  (hidden comment: CN2)
Q43  USERCOMPTEXT3: TOSHIBA  VAL3: TPH8R903NL  (hidden comment: MFNKR2)
Q44  USERCOMPTEXT3: TOSHIBA  VAL3: TPH2R003PL  (hidden comment: MFNKR2)
Q45  USERCOMPTEXT3: TOSHIBA  VAL3: TPH8R903NL  (hidden comment: MFNKR2)
Q46  USERCOMPTEXT3: TOSHIBA  VAL3: TPH4R803PL  (hidden comment: MFNKR2)
R349  VAL1: 2.2(J)  (hidden comment: R)
R350  VAL1: 2.2(J)  (hidden comment: R)
R351  VAL1: 1.5K(F)  (hidden comment: R)
R352  VAL1: 1.5K(F)  (hidden comment: R)
R353  VAL1: 100K(J)  (hidden comment: R)
R354  NOTMOUNT: NOT MOUNT  (hidden comment: R)
R355  VAL1: 100K(J)  (hidden comment: R)
R356  NOTMOUNT: NOT MOUNT  (hidden comment: R)
R357  VAL1: 27K(F)  (hidden comment: R)
R358  VAL1: 160K(F)  (hidden comment: R)
R359  VAL1: 27K(F)  (hidden comment: R)
R360  VAL1: 160K(F)  (hidden comment: R)
R361  VAL1: 0  (hidden comment: R)
R362  VAL1: 0  (hidden comment: R)
R363  VAL1: 0  (hidden comment: R)
R364  VAL1: 0  (hidden comment: R)
R365  VAL1: 0  (hidden comment: R)
R366  VAL1: 0  (hidden comment: R)
R367  VAL1: 0  (hidden comment: R)
R368  VAL1: 0  (hidden comment: R)
R371  NOTMOUNT: NOT MOUNT  (hidden comment: R)
R372  NOTMOUNT: NOT MOUNT  (hidden comment: R)
R373  VAL1: 2.2K(F)  (hidden comment: R)
R374  VAL1: 2.2K(F)  (hidden comment: R)
R375  VAL1: 3.3K(D)  (hidden comment: R)
R376  VAL1: 82K(D)  (hidden comment: R)
R377  VAL1: 3.3K(D)  (hidden comment: R)
R378  VAL1: 82K(D)  (hidden comment: R)
R379  NOTMOUNT: NOT MOUNT  (hidden comment: R)
R380  VAL1: 12K(D)  (hidden comment: R)
R381  NOTMOUNT: NOT MOUNT  (hidden comment: R)
R382  VAL1: 12K(D)  (hidden comment: R)
U?#15  DATE: 2021/10/15  SHEETNUMBER: 15/16  TITLE: Non Isolated Buck / DC-DC Converter  REVISION: 01  DRAWINGNUMBER: RD205-SCHEMATIC-01  FUNCTION: +1.05V10A  (hidden comment: WAKU_DEF100)

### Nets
GND_22: C369.1 C371.1 C373.1 C375.1 C377.1 C379.1 C381.1 C383.1 C389.1 C391.1 C395.1 C397.1 C421.1 C424.1 C469.1 C470.1 C517.1 E44.1 IC22.10 IC22.17 PJ22.2 Q44.1 Q44.2 Q44.3 R354.1 R358.1 R367.1 R376.1 R380.1 ; off-sheet GND_22
GND_23: C370.1 C372.1 C374.1 C376.1 C378.1 C380.1 C382.1 C384.1 C390.1 C392.1 C396.1 C398.1 C422.1 C425.1 C471.1 C472.1 C518.1 E46.1 IC23.10 IC23.17 PJ23.2 Q46.1 Q46.2 Q46.3 R356.1 R360.1 R368.1 R378.1 R382.1 ; off-sheet GND_23
SIGN2069: C387.2 C470.2 IC22.4 R371.2 R373.1
SIGN2071: C382.2 IC23.8 IC23.14 R350.2
SIGN2072: C379.2 IC22.7 R351.2
SIGN2073: C388.2 C472.2 IC23.4 R372.2 R374.1
SIGN2074: C377.2 R351.1
SIGN2075: IC22.1 R365.1
SIGN2076: IC22.11 R353.1 R354.2
SIGN2077: C391.2 C393.1 IC22.6 R375.1 R376.2 R379.1 R380.2
SIGN2078: C378.2 R352.1
SIGN2079: IC23.11 R355.1 R356.2
SIGN2080: C380.2 IC23.7 R352.2
SIGN2081: IC23.9 R359.2
SIGN2082: C386.1 D23.C R363.2
SIGN2085: C383.2 D22.A IC22.12 R353.2
SIGN2089: C376.2 IC23.3
SIGN2091: C381.2 IC22.8 IC22.14 R349.2
SIGN2093: IC23.13 R368.2
SIGN2096: IC22.9 R357.2
SIGN2097: C375.2 IC22.3
SIGN2098: IC22.13 R367.2
SIGN2099: IC23.1 R366.1
SIGN2145: C385.1 D22.C R361.2
SIGN2146: C384.2 D23.A IC23.12 R355.2
SIGN2294: Q44.4 R362.2
SIGN2295: Q43.4 R365.2
SIGN2296: Q45.4 R366.2
SIGN2297: Q46.4 R364.2
SIGN2298: C385.2 IC22.2 L22.1 Q43.1 Q43.2 Q43.3 Q44.5 Q44.6 Q44.7 Q44.8 R373.2
SIGN2299: C386.2 IC23.2 L23.1 Q45.1 Q45.2 Q45.3 Q46.5 Q46.6 Q46.7 Q46.8 R374.2
SIGN2310: C392.2 C394.1 IC23.6 R377.1 R378.2 R381.1 R382.2
VP_1R05_VOUT_22: C387.1 C393.2 C395.2 C397.2 C421.2 C424.2 C469.2 C517.2 E43.1 IC22.5 L22.2 R371.1 R375.2 R379.2 ; off-sheet VP_1R05_VOUT_22
VP_1R05_VOUT_23: C388.1 C394.2 C396.2 C398.2 C422.2 C425.2 C471.2 C518.2 E45.1 IC23.5 L23.2 R372.1 R377.2 R381.2 ; off-sheet VP_1R05_VOUT_23
VP_12R0_VIN_22: C369.2 C371.2 C373.2 C389.2 PJ22.1 Q43.5 Q43.6 Q43.7 Q43.8 R349.1 ; off-sheet VP_12R0_VIN_22
VP_12R0_VIN_23: C370.2 C372.2 C374.2 C390.2 PJ23.1 Q45.5 Q45.6 Q45.7 Q45.8 R350.1 ; off-sheet VP_12R0_VIN_23
NetIC22_15: IC22.15 R362.1
NetIC22_16: IC22.16 R361.1
NetIC23_15: IC23.15 R364.1
NetIC23_16: IC23.16 R363.1
NetR357_1: R357.1 R358.2
NetR359_1: R359.1 R360.2

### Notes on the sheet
- Unless otherwise specified
- Resistors 1/16W (1608)
- Capacitors 50V (1608)
- temperature characteristics X5R
- DC+12V
- INPUT
- (near E43) +1.05V 10A 100%LOAD
- (near E43) OUTPUT
- (near IC22) 200kHz
- (near E44) GND
- (near E45) +1.05V 10A 50%LOAD
- (near E45) OUTPUT
- (near IC23) 200kHz
- (near E46) GND

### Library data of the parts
C369 C370 = C: as C318 on sheet 13
C371-C374 = C: as C320-C323 on sheet 13
C375-C378 C385 C386 C389 C390 = C: as C324-C327 on sheet 13
C379 C380 = C: SQ_PART_MODEL: CON_470p; FNPARTSNAMEG: CHIP CERAMIC CAPACITOR (1608); USEINPARTSLIST: YES; OriginalSymbolOrigin: (2540,7620); TOLERANCE: J; ASIMVALUE: 470P; CDMASTERCADCELG: C8100E; MFSOLDERINGPROP: .; TEMPCHARACTERI2: CH; MFFORMINGDIVP: KC; OUMECLASSIFICATION: セラミックコンデンサ; SIZECODESMD: 1608; MFMOUNTSYMBOLP: 80; PCODE: P03039329128; FNCLASSCODEG: P03-03; MAXGCOUNT: 1; RATEDVOLTAGE: 50; COMPONENTNAME: G36030011372; OUMEMAKER: KYC 京セラ; MFPACKAGEMETHOP: S; OUMEMAKERKATAMEI: CM105CH471J50AT
C381 C382 = C: as C330 on sheet 13
C383 C384 = C: as C332 on sheet 13
C387 C388 = C: SQ_PART_MODEL: CON_470n; FNPARTSNAMEG: CHIP CERAMIC CAPACITOR (1608); USEINPARTSLIST: YES; OriginalSymbolOrigin: (2540,7620); MFSOLDERINGPROP: .; TEMPCHARACTERI2: B; MFFORMINGDIVP: KC; OUMECLASSIFICATION: セラミックコンデンサ; SIZECODESMD: 1608; MFMOUNTSYMBOLP: 80; CDMASTERCADCELG: C8100E; PCODE: P03039ABG127; FNCLASSCODEG: P03-03; MAXGCOUNT: 1; RATEDVOLTAGE: 10; COMPONENTNAME: GDM030001129; OUMEMAKER: KYC 京セラ; MFPACKAGEMETHOP: S; NOMINALCAPACITA: 470n; OUMEMAKERKATAMEI: CM105B474K10AT; CAPACITANCETOLE: K
C391-C394 = C: as C340-C343 on sheet 13
C395 C396 C421 C422 C424 C425 = C: as C344 on sheet 13
C397 C398 = C: as C346 on sheet 13
C469-C472 = C: as C463-C466 on sheet 13
C517 C518 = C: as C511-C514 on sheet 13
D22 D23 = D: as D19 on sheet 13
E43-E46 = EB: as E37-E40 on sheet 13
IC22 IC23 = LTC7803UD: as IC19 on sheet 13
L22 L23 = L: USEINPARTSLIST: YES; PARTNAME: 74439369033; OriginalSymbolOrigin: (2540,5080); MAXGCOUNT: 1; COMPONENTNAME: L_L; OUMEMAKER: WURTH
PJ22 PJ23 = CN2: as PJ19 on sheet 13
Q43-Q46 = MFNKR2: as Q37-Q40 on sheet 13
R349 R350 = R: as R298 on sheet 13
R351 R352 = R: SQ_PART_MODEL: RES_1.5K; FNPARTSNAMEG: CHIP RESISTOR (1608); USEINPARTSLIST: YES; OriginalSymbolOrigin: (5080,5080); TOLERANCE: F; ASIMVALUE: 1.5K; MAXGCOUNT: 1; COMPONENTNAME: G36010027232; MFSOLDERINGPROP: .; OUMEMAKER: HDK 北陸電気工業; MFPACKAGEMETHOP: S; MFFORMINGDIVP: KC; MOUNTINGFORMSMD: SMD; OUMECLASSIFICATION: 表面実装用固定抵抗器; MFMOUNTSYMBOLP: 80; POWERRATING: 63m; OUMEMAKERKATAMEI: CR1/16 152FV; NUMBEROFELEMENT: 0; VAL2: 62.5mW; CDMASTERCADCELG: DR802R; PCODE: P01042512223; FNCLASSCODEG: P01-08
R353 R355 = R: SQ_PART_MODEL: RES_100K; FNPARTSNAMEG: CHIP RESISTOR (1608); USEINPARTSLIST: YES; OriginalSymbolOrigin: (5080,5080); TOLERANCE: F; ASIMVALUE: 100K; MFSOLDERINGPROP: .; MFPACKAGEMETHOP: S; MFFORMINGDIVP: KC; MOUNTINGFORMSMD: SMD; MFMOUNTSYMBOLP: 80; NUMBEROFELEMENT: 0; PCODE: P01042045226; MAXGCOUNT: 1; COMPONENTNAME: G36010011057; OUMEMAKER: HDK 北陸電気工業; OUMECLASSIFICATION: 表面実装用固定抵抗器; POWERRATING: 63m; OUMEMAKERKATAMEI: CR1/16 104FV; VAL2: 62.5mW; CDMASTERCADCELG: DR802R; FNCLASSCODEG: P01-08
R354 R356 = R: as R303 on sheet 13
R357 R359 = R: SQ_PART_MODEL: RES_27K; FNPARTSNAMEG: CHIP RESISTOR (1608); USEINPARTSLIST: YES; OriginalSymbolOrigin: (5080,5080); MAXGCOUNT: 1; TOLERANCE: F; COMPONENTNAME: G36010104117; MFSOLDERINGPROP: .; OUMEMAKER: NAE 松下電子部品; MFPACKAGEMETHOP: S; MFFORMINGDIVP: KC; MOUNTINGFORMSMD: SMD; OUMECLASSIFICATION: 表面実装用固定抵抗器; ASIMVALUE: 27K; MFMOUNTSYMBOLP: 80; POWERRATING: 63m; OUMEMAKERKATAMEI: ERJ3GEYF273V; NUMBEROFELEMENT: 0; VAL2: 62.5mW; CDMASTERCADCELG: DR802R; PCODE: P01042508622; FNCLASSCODEG: P01-08
R358 R360 = R: SQ_PART_MODEL: RES_160K; FNPARTSNAMEG: CHIP RESISTOR (1608); USEINPARTSLIST: YES; OriginalSymbolOrigin: (5080,5080); MAXGCOUNT: 1; COMPONENTNAME: G36010104223; MFSOLDERINGPROP: .; OUMEMAKER: HDK 北陸電気工業; MFPACKAGEMETHOP: S; MFFORMINGDIVP: KC; MOUNTINGFORMSMD: SMD; OUMECLASSIFICATION: 表面実装用固定抵抗器; RESISTANCETOLER: F; MFMOUNTSYMBOLP: 80; POWERRATING: 63m; OUMEMAKERKATAMEI: CR1/16 164FV; NOMINALRESISTAN: 160K; NUMBEROFELEMENT: 0; VAL2: 62.5mW; CDMASTERCADCELG: DR802R; PCODE: P01042125225; FNCLASSCODEG: P01-08
R361 R363 R367 R368 = R: as R310 on sheet 13
R362 R364-R366 = R: as R311 on sheet 13
R371 R372 = R: as R320 on sheet 13
R373 R374 = R: SQ_PART_MODEL: RES_2.2K; FNPARTSNAMEG: CHIP RESISTOR (1608); USEINPARTSLIST: YES; OriginalSymbolOrigin: (5080,5080); PCODE: P01042159428; MAXGCOUNT: 1; COMPONENTNAME: G36010027249; MFSOLDERINGPROP: .; OUMEMAKER: KOA ＫＯＡ; MFPACKAGEMETHOP: S; MFFORMINGDIVP: KC; MOUNTINGFORMSMD: SMD; OUMECLASSIFICATION: 表面実装用固定抵抗器; RESISTANCETOLER: F; MFMOUNTSYMBOLP: 80; POWERRATING: 63m; OUMEMAKERKATAMEI: RK73H1JTD2201F; NOMINALRESISTAN: 2.2K; NUMBEROFELEMENT: 0; VAL2: 62.5mW; CDMASTERCADCELG: DR802R; FNCLASSCODEG: P01-08
R375 R377 = R: SQ_PART_MODEL: RES_3.3K; FNPARTSNAMEG: CHIP RESISTOR (1608); USEINPARTSLIST: YES; OriginalSymbolOrigin: (5080,5080); MAXGCOUNT: 1; COMPONENTNAME: G36010014485; MFSOLDERINGPROP: .; OUMEMAKER: SSM 進工業; MFPACKAGEMETHOP: S; MFFORMINGDIVP: KC; MOUNTINGFORMSMD: SMD; OUMECLASSIFICATION: 表面実装用固定抵抗器; RESISTANCETOLER: D; MFMOUNTSYMBOLP: 80; POWERRATING: 63m; OUMEMAKERKATAMEI: RR0816P-332-D; NOMINALRESISTAN: 3.3K; NUMBEROFELEMENT: 0; VAL2: 62.5mW; CDMASTERCADCELG: DR802R; PCODE: P01042249822; FNCLASSCODEG: P01-08
R376 R378 = R: ICX_PART_MODEL: RES_82K; FNPARTSNAMEG: CHIP RESISTOR (1608); OriginalSymbolOrigin: (5080,5080); FNCLASSCODEG: P01-08; PCODE: P01117075110; CDMASTERCADCELG: DR802R; USEWITHSCHEMA: YES; VAL2: 62.5mW; NUMBEROFELEMENT: 0; NOMINALRESISTAN: 82K; OUMEMAKERKATAMEI: RK73G1JTD823D; POWERRATING: 63m; MFMOUNTSYMBOLP: 80; RESISTANCETOLER: D; FUNCTION: G36010129714; OUMECLASSIFICATION: 表面実装用固定抵抗器; MOUNTINGFORMSMD: SMD; MFFORMINGDIVP: KC; MFPACKAGEMETHOP: S; OUMEMAKER: KOA ＫＯＡ; MFSOLDERINGPROP: .; MAXGCOUNT: 1
R379 R381 = R: as R328 on sheet 13
R380 R382 = R: ICX_PART_MODEL: RES_12K; FNPARTSNAMEG: CHIP RESISTOR (1608); OriginalSymbolOrigin: (5080,5080); FNCLASSCODEG: P01-08; PCODE: P01117055112; CDMASTERCADCELG: DR802R; USEWITHSCHEMA: YES; VAL2: 62.5mW; NUMBEROFELEMENT: 0; NOMINALRESISTAN: 12K; OUMEMAKERKATAMEI: RK73G1JTD123D; POWERRATING: 63m; MFMOUNTSYMBOLP: 80; RESISTANCETOLER: D; FUNCTION: G36010129516; OUMECLASSIFICATION: 表面実装用固定抵抗器; MOUNTINGFORMSMD: SMD; MFFORMINGDIVP: KC; MFPACKAGEMETHOP: S; OUMEMAKER: KOA ＫＯＡ; MFSOLDERINGPROP: .; MAXGCOUNT: 1
U?#15 = WAKU_DEF100: PLOTTIME: HH:MM; SAVEAREA0: 330961,54,387907,31546; TIME: 19:23:07; UPDATEUSER: t5459927; UPDATETIME: 15:33:43; SAVECOUNT: 6; OriginalSymbolOrigin: (10160,284480); DESIGNED: ***

## Sheet 16.SchDoc
size 398 x 287 mm
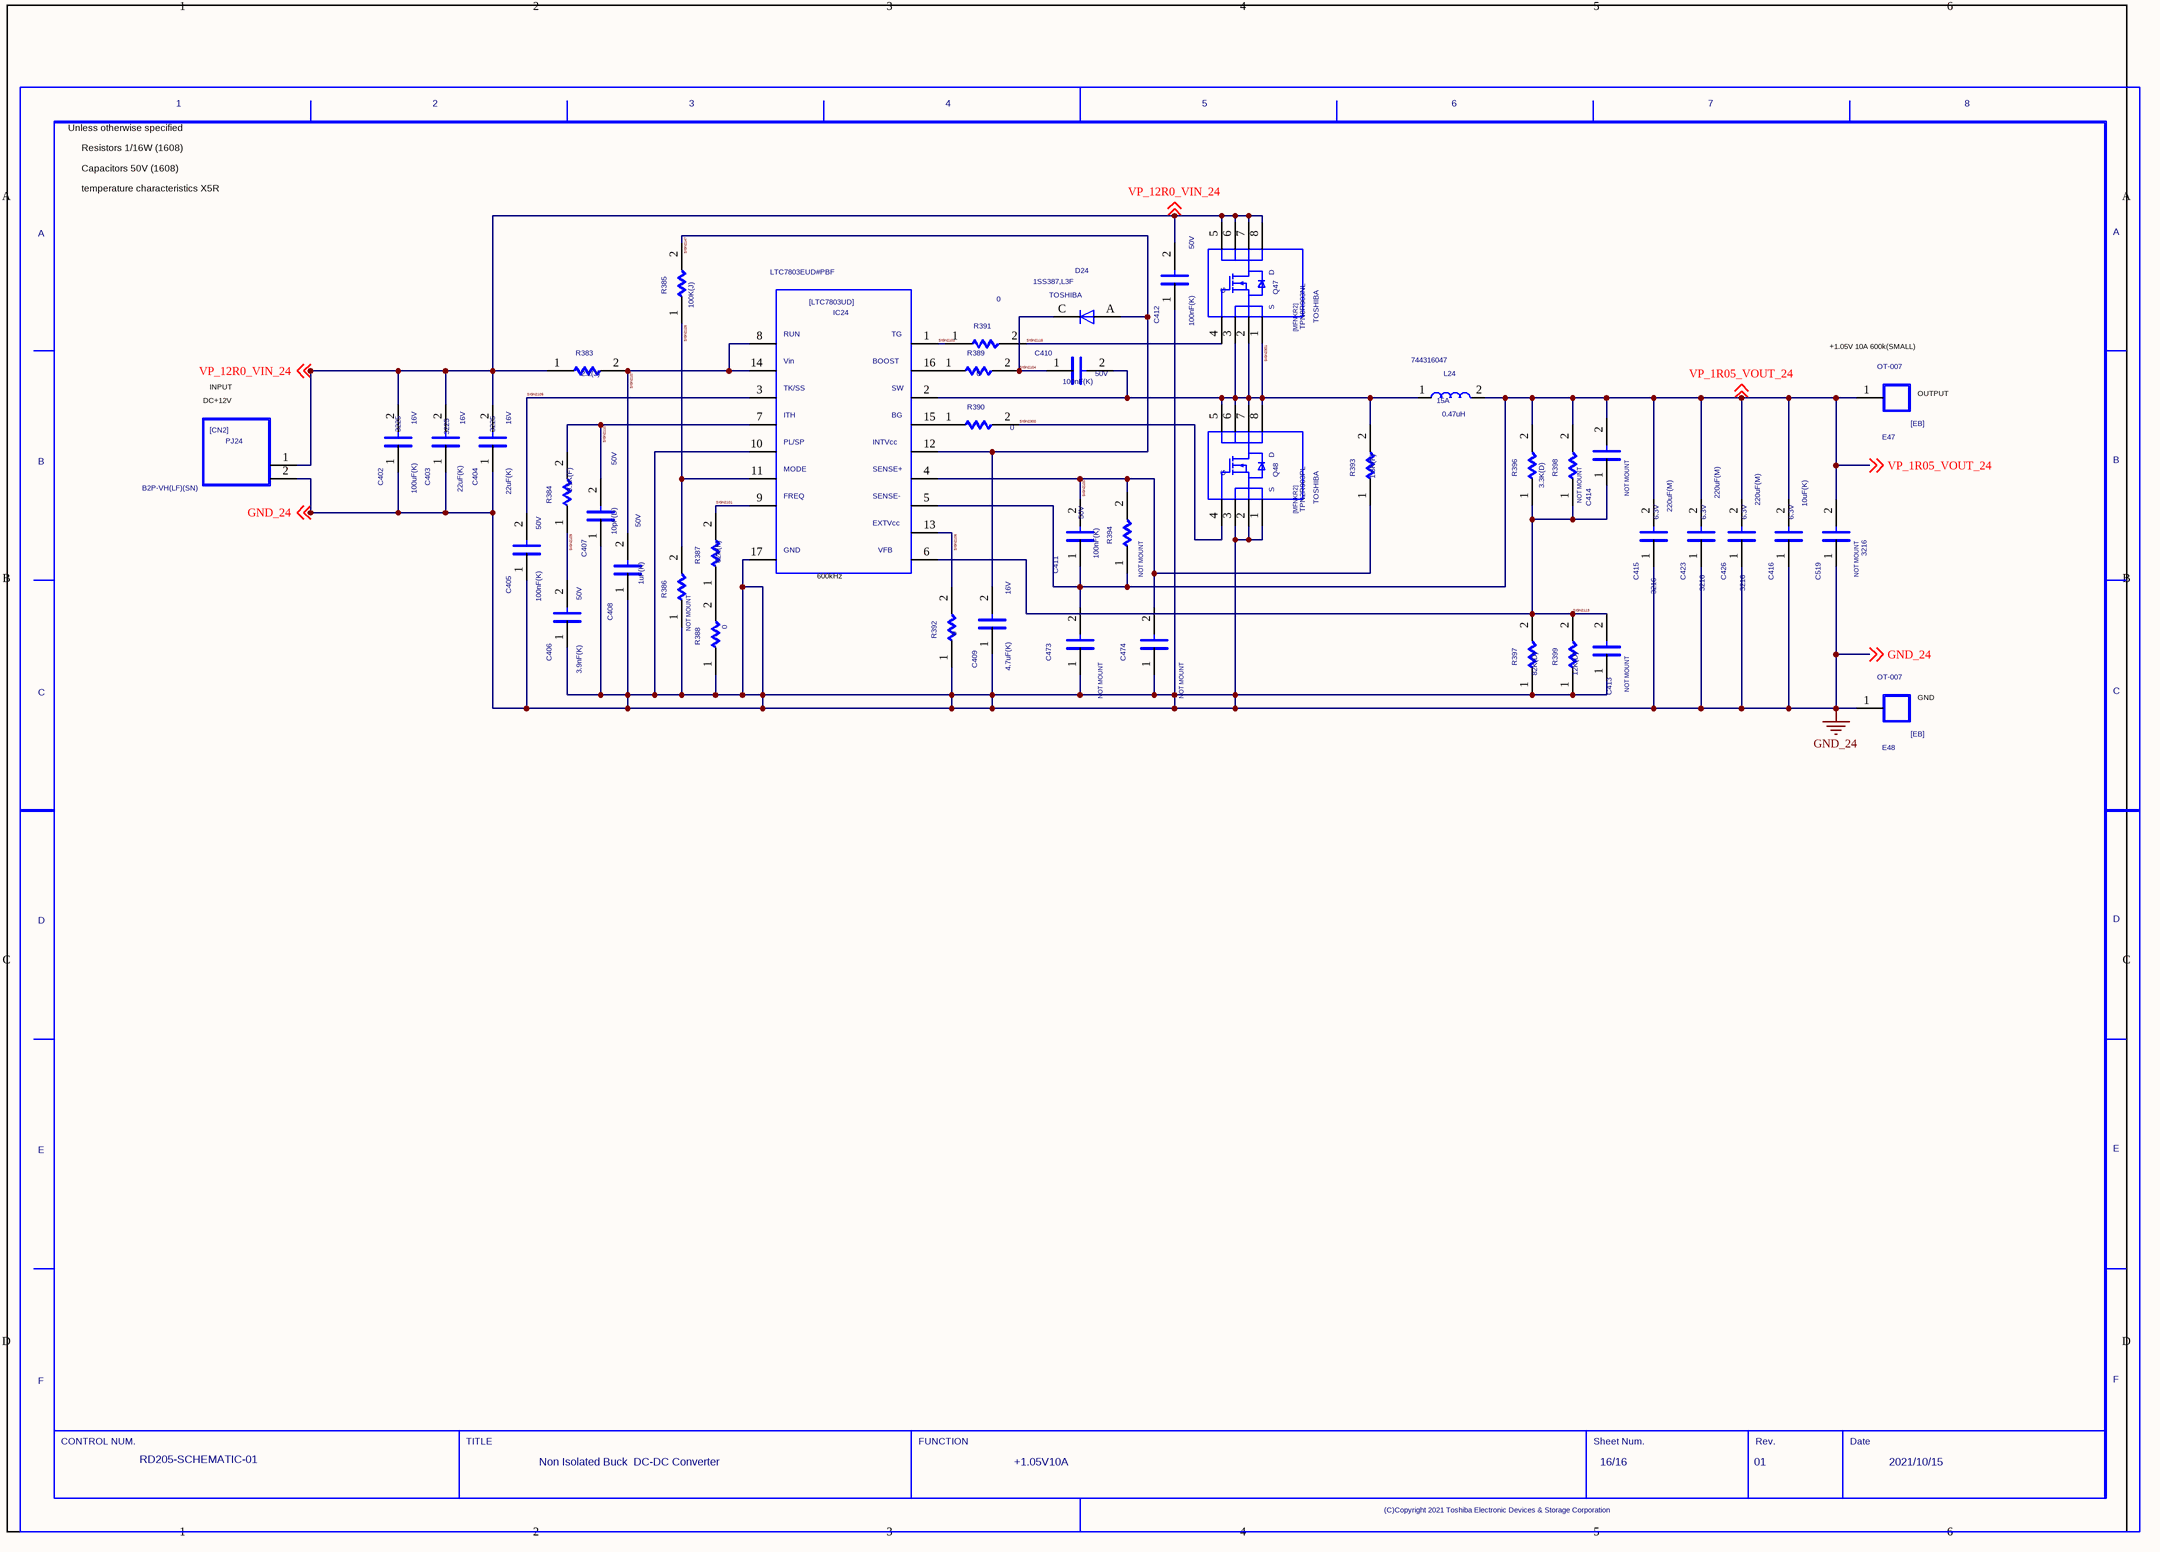
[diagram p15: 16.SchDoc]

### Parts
(Parts that share a designator on the sheet are numbered #1, #2 ... from top to bottom, then left to right.)
C402  SIZECODESMD: 3225  VAL2: 16V  VAL1: 100uF(K)  (hidden comment: C)
C403  SIZECODESMD: 3225  VAL2: 16V  VAL1: 22uF(K)  (hidden comment: C)
C404  SIZECODESMD: 3225  VAL2: 16V  VAL1: 22uF(K)  (hidden comment: C)
C405  VAL2: 50V  VAL1: 100nF(K)  (hidden comment: C)
C406  VAL2: 50V  VAL1: 3.9nF(K)  (hidden comment: C)
C407  VAL2: 50V  VAL1: 10pF(D)  (hidden comment: C)
C408  VAL2: 50V  VAL1: 1uF(K)  (hidden comment: C)
C409  VAL2: 16V  VAL1: 4.7uF(K)  (hidden comment: C)
C410  VAL2: 50V  VAL1: 100nF(K)  (hidden comment: C)
C411  VAL2: 50V  VAL1: 100nF(K)  (hidden comment: C)
C412  VAL2: 50V  VAL1: 100nF(K)  (hidden comment: C)
C413  NOTMOUNT: NOT MOUNT  (hidden comment: C)
C414  NOTMOUNT: NOT MOUNT  (hidden comment: C)
C415  SIZECODESMD: 3216  VAL2: 6.3V  VAL1: 220uF(M)  (hidden comment: C)
C416  VAL2: 6.3V  VAL1: 10uF(K)  (hidden comment: C)
C423  SIZECODESMD: 3216  VAL2: 6.3V  VAL1: 220uF(M)  (hidden comment: C)
C426  SIZECODESMD: 3216  VAL2: 6.3V  VAL1: 220uF(M)  (hidden comment: C)
C473  NOTMOUNT: NOT MOUNT  (hidden comment: C)
C474  NOTMOUNT: NOT MOUNT  (hidden comment: C)
C519  NOTMOUNT: NOT MOUNT  SIZECODESMD: 3216  (hidden comment: C)
D24  USERCOMPTEXT3: TOSHIBA  VAL3: 1SS387,L3F  (hidden comment: D)
E47  VAL3: OT-007  (hidden comment: EB)
E48  VAL3: OT-007  (hidden comment: EB)
IC24  VAL3: LTC7803EUD#PBF  (hidden comment: LTC7803UD)
L24  VAL3: 744316047  VAL2: 15A  VAL1: 0.47uH  (hidden comment: L)
PJ24  VAL3: B2P-VH(LF)(SN)  (hidden comment: CN2)
Q47  USERCOMPTEXT3: TOSHIBA  VAL3: TPN8R903NL  (hidden comment: MFNKR2)
Q48  USERCOMPTEXT3: TOSHIBA  VAL3: TPN2R903PL  (hidden comment: MFNKR2)
R383  VAL1: 2.2(J)  (hidden comment: R)
R384  VAL1: 9.1K(F)  (hidden comment: R)
R385  VAL1: 100K(J)  (hidden comment: R)
R386  NOTMOUNT: NOT MOUNT  (hidden comment: R)
R387  VAL1: 62K(F)  (hidden comment: R)
R388  VAL1: 0  (hidden comment: R)
R389  VAL1: 0  (hidden comment: R)
R390  VAL1: 0  (hidden comment: R)
R391  VAL1: 0  (hidden comment: R)
R392  VAL1: 0  (hidden comment: R)
R393  VAL1: 1.6K(F)  (hidden comment: R)
R394  NOTMOUNT: NOT MOUNT  (hidden comment: R)
R396  VAL1: 3.3K(D)  (hidden comment: R)
R397  VAL1: 82K(D)  (hidden comment: R)
R398  NOTMOUNT: NOT MOUNT  (hidden comment: R)
R399  VAL1: 12K(D)  (hidden comment: R)
U?#16  DATE: 2021/10/15  SHEETNUMBER: 16/16  TITLE: Non Isolated Buck / DC-DC Converter  REVISION: 01  DRAWINGNUMBER: RD205-SCHEMATIC-01  FUNCTION: +1.05V10A  (hidden comment: WAKU_DEF100)

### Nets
GND_24: C402.1 C403.1 C404.1 C405.1 C406.1 C407.1 C408.1 C409.1 C412.1 C413.1 C415.1 C416.1 C423.1 C426.1 C473.1 C474.1 C519.1 E48.1 IC24.10 IC24.17 PJ24.2 Q48.1 Q48.2 Q48.3 R386.1 R388.1 R392.1 R397.1 R399.1 ; off-sheet GND_24
SIGN2100: C411.2 C474.2 IC24.4 R393.1 R394.2
SIGN2101: IC24.9 R387.2
SIGN2103: IC24.1 R391.1
SIGN2104: C410.1 D24.C R389.2
SIGN2105: C405.2 IC24.3
SIGN2106: IC24.13 R392.2
SIGN2107: C408.2 IC24.8 IC24.14 R383.2
SIGN2109: C406.2 R384.1
SIGN2110: C407.2 IC24.7 R384.2
SIGN2113: C413.2 C414.1 IC24.6 R396.1 R397.2 R398.1 R399.2
SIGN2115: Q47.4 R391.2
SIGN2126: IC24.11 R385.1 R386.2
SIGN2147: C409.2 D24.A IC24.12 R385.2
SIGN2300: Q48.4 R390.2
SIGN2301: C410.2 IC24.2 L24.1 Q47.1 Q47.2 Q47.3 Q48.5 Q48.6 Q48.7 Q48.8 R393.2
VP_1R05_VOUT_24: C411.1 C414.2 C415.2 C416.2 C423.2 C426.2 C473.2 C519.2 E47.1 IC24.5 L24.2 R394.1 R396.2 R398.2 ; off-sheet VP_1R05_VOUT_24
VP_12R0_VIN_24: C402.2 C403.2 C404.2 C412.2 PJ24.1 Q47.5 Q47.6 Q47.7 Q47.8 R383.1 ; off-sheet VP_12R0_VIN_24
NetIC24_15: IC24.15 R390.1
NetIC24_16: IC24.16 R389.1
NetR387_1: R387.1 R388.2

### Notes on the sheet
- Unless otherwise specified
- Resistors 1/16W (1608)
- Capacitors 50V (1608)
- temperature characteristics X5R
- DC+12V
- INPUT
- (near E47) +1.05V 10A 600k(SMALL)
- (near E47) OUTPUT
- (near IC24) 600kHz
- (near E48) GND

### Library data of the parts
C402 = C: as C318 on sheet 13
C403 C404 = C: as C320-C323 on sheet 13
C405 C410 C412 = C: as C324-C327 on sheet 13
C406 = C: SQ_PART_MODEL: CON_3.9n; FNPARTSNAMEG: CHIP CERAMIC CAPACITOR (1608); USEINPARTSLIST: YES; OriginalSymbolOrigin: (2540,7620); TOLERANCE: K; ASIMVALUE: 3.9N; MFSOLDERINGPROP: .; TEMPCHARACTERI2: B; MFFORMINGDIVP: KC; OUMECLASSIFICATION: セラミックコンデンサ; SIZECODESMD: 1608; MFMOUNTSYMBOLP: 80; CDMASTERCADCELG: C8100E; PCODE: P03039077227; FNCLASSCODEG: P03-03; MAXGCOUNT: 1; RATEDVOLTAGE: 50; COMPONENTNAME: G36030011242; OUMEMAKER: MRT 村田製作所; MFPACKAGEMETHOP: S; OUMEMAKERKATAMEI: GRM39B392K50PT
C407 = C: SQ_PART_MODEL: CON_10p; FNPARTSNAMEG: CHIP CERAMIC CAPACITOR (1608); USEINPARTSLIST: YES; OriginalSymbolOrigin: (2540,7620); TOLERANCE: D; ASIMVALUE: 10P; MFSOLDERINGPROP: .; TEMPCHARACTERI2: CH; MFFORMINGDIVP: KC; OUMECLASSIFICATION: セラミックコンデンサ; SIZECODESMD: 1608; MFMOUNTSYMBOLP: 80; CDMASTERCADCELG: C8100E; PCODE: P03039185229; FNCLASSCODEG: P03-03; MAXGCOUNT: 1; RATEDVOLTAGE: 50; COMPONENTNAME: G36030011013; OUMEMAKER: MRT 村田製作所; MFPACKAGEMETHOP: S; OUMEMAKERKATAMEI: GRM39CH100D50PT
C408 = C: as C330 on sheet 13
C409 = C: as C332 on sheet 13
C411 = C: as C360 on sheet 14
C413 C414 = C: as C340-C343 on sheet 13
C415 C423 C426 = C: as C344 on sheet 13
C416 = C: as C365 on sheet 14
C473 C474 = C: as C463-C466 on sheet 13
C519 = C: as C511-C514 on sheet 13
D24 = D: as D19 on sheet 13
E47 E48 = EB: as E37-E40 on sheet 13
IC24 = LTC7803UD: as IC19 on sheet 13
L24 = L: USEINPARTSLIST: YES; PARTNAME: 744316033; OriginalSymbolOrigin: (2540,5080); MAXGCOUNT: 1; COMPONENTNAME: L_L; OUMEMAKER: WURTH
PJ24 = CN2: as PJ19 on sheet 13
Q47 Q48 = MFNKR2: as Q41 on sheet 14
R383 = R: as R298 on sheet 13
R384 = R: SQ_PART_MODEL: RES_9.1K; FNPARTSNAMEG: CHIP RESISTOR (1608); USEINPARTSLIST: YES; OriginalSymbolOrigin: (5080,5080); MAXGCOUNT: 1; COMPONENTNAME: G36010104414; MFSOLDERINGPROP: .; OUMEMAKER: HDK 北陸電気工業; MFPACKAGEMETHOP: S; MFFORMINGDIVP: KC; MOUNTINGFORMSMD: SMD; OUMECLASSIFICATION: 表面実装用固定抵抗器; RESISTANCETOLER: F; MFMOUNTSYMBOLP: 80; POWERRATING: 63m; OUMEMAKERKATAMEI: CR1/16 912FV; NOMINALRESISTAN: 9.1K; NUMBEROFELEMENT: 0; VAL2: 62.5mW; CDMASTERCADCELG: DR802R; PCODE: P01042501227; FNCLASSCODEG: P01-08
R385 = R: as R302 on sheet 13
R386 = R: as R303 on sheet 13
R387 = R: as R336 on sheet 14
R388 = R: as R337 on sheet 14
R389 R392 = R: as R310 on sheet 13
R390 R391 = R: as R311 on sheet 13
R393 = R: SQ_PART_MODEL: RES_1.6K; FNPARTSNAMEG: CHIP RESISTOR (1608); USEINPARTSLIST: YES; OriginalSymbolOrigin: (5080,5080); MAXGCOUNT: 1; COMPONENTNAME: G51011055107; MFSOLDERINGPROP: .; OUMEMAKER: HDK 北陸電気工業; MFPACKAGEMETHOP: S; MFFORMINGDIVP: KC; MOUNTINGFORMSMD: SMD; OUMECLASSIFICATION: 表面実装用固定抵抗器; RESISTANCETOLER: F; MFMOUNTSYMBOLP: 80; POWERRATING: 63m; OUMEMAKERKATAMEI: CR1/16 162FV; NOMINALRESISTAN: 1.6K; NUMBEROFELEMENT: 0; VAL2: 62.5mW; CDMASTERCADCELG: DR802R; PCODE: P01042026225; FNCLASSCODEG: P01-08
R394 = R: SQ_PART_MODEL: RES_68K; FNPARTSNAMEG: CHIP RESISTOR (1608); USEINPARTSLIST: YES; OriginalSymbolOrigin: (5080,5080); MAXGCOUNT: 1; COMPONENTNAME: G36010027126; OUMEMAKER: HDK 北陸電気工業; MOUNTINGFORMSMD: SMD; OUMECLASSIFICATION: 表面実装用固定抵抗器; RESISTANCETOLER: F; POWERRATING: 63m; OUMEMAKERKATAMEI: CR1/16 683FV; NOMINALRESISTAN: 68K; CDMASTERCADCELG: DR802R; MFSOLDERINGPROP: .; MFPACKAGEMETHOP: S; MFFORMINGDIVP: KC; MFMOUNTSYMBOLP: 80; NUMBEROFELEMENT: 0; VAL2: 62.5mW; VAL1: 68K(F); PCODE: P01042456220; FNCLASSCODEG: P01-08
R396 = R: as R375 on sheet 15
R397 = R: ICX_PART_MODEL: RES_82K; FNPARTSNAMEG: CHIP RESISTOR (1608); OriginalSymbolOrigin: (5080,5080); FNCLASSCODEG: P01-08; PCODE: P01042604621; CDMASTERCADCELG: DR802R; USEWITHSCHEMA: YES; VAL2: 62.5mW; NUMBEROFELEMENT: 0; NOMINALRESISTAN: 82K; OUMEMAKERKATAMEI: ERA3YKD823V; POWERRATING: 63m; MFMOUNTSYMBOLP: 80; RESISTANCETOLER: D; FUNCTION: G36010014829; OUMECLASSIFICATION: 表面実装用固定抵抗器; MOUNTINGFORMSMD: SMD; MFFORMINGDIVP: KC; MFPACKAGEMETHOP: S; OUMEMAKER: NAE 松下電子部品; MFSOLDERINGPROP: .; MAXGCOUNT: 1
R398 = R: as R328 on sheet 13
R399 = R: as R380 on sheet 15
U?#16 = WAKU_DEF100: as U?#15 on sheet 15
